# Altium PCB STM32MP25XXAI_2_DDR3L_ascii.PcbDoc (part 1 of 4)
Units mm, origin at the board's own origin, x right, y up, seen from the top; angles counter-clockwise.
Board outline 172 x 137 mm, 6 copper layers (Top Layer, Signal Layer 1, Signal Layer 2, Signal Layer 3, Signal Layer 4, Bottom Layer), stack 2.079 mm thick; 237 components, 152 nets, 1304 pads, 909 vias.
Unrouted connection lines stored in the file: 13.
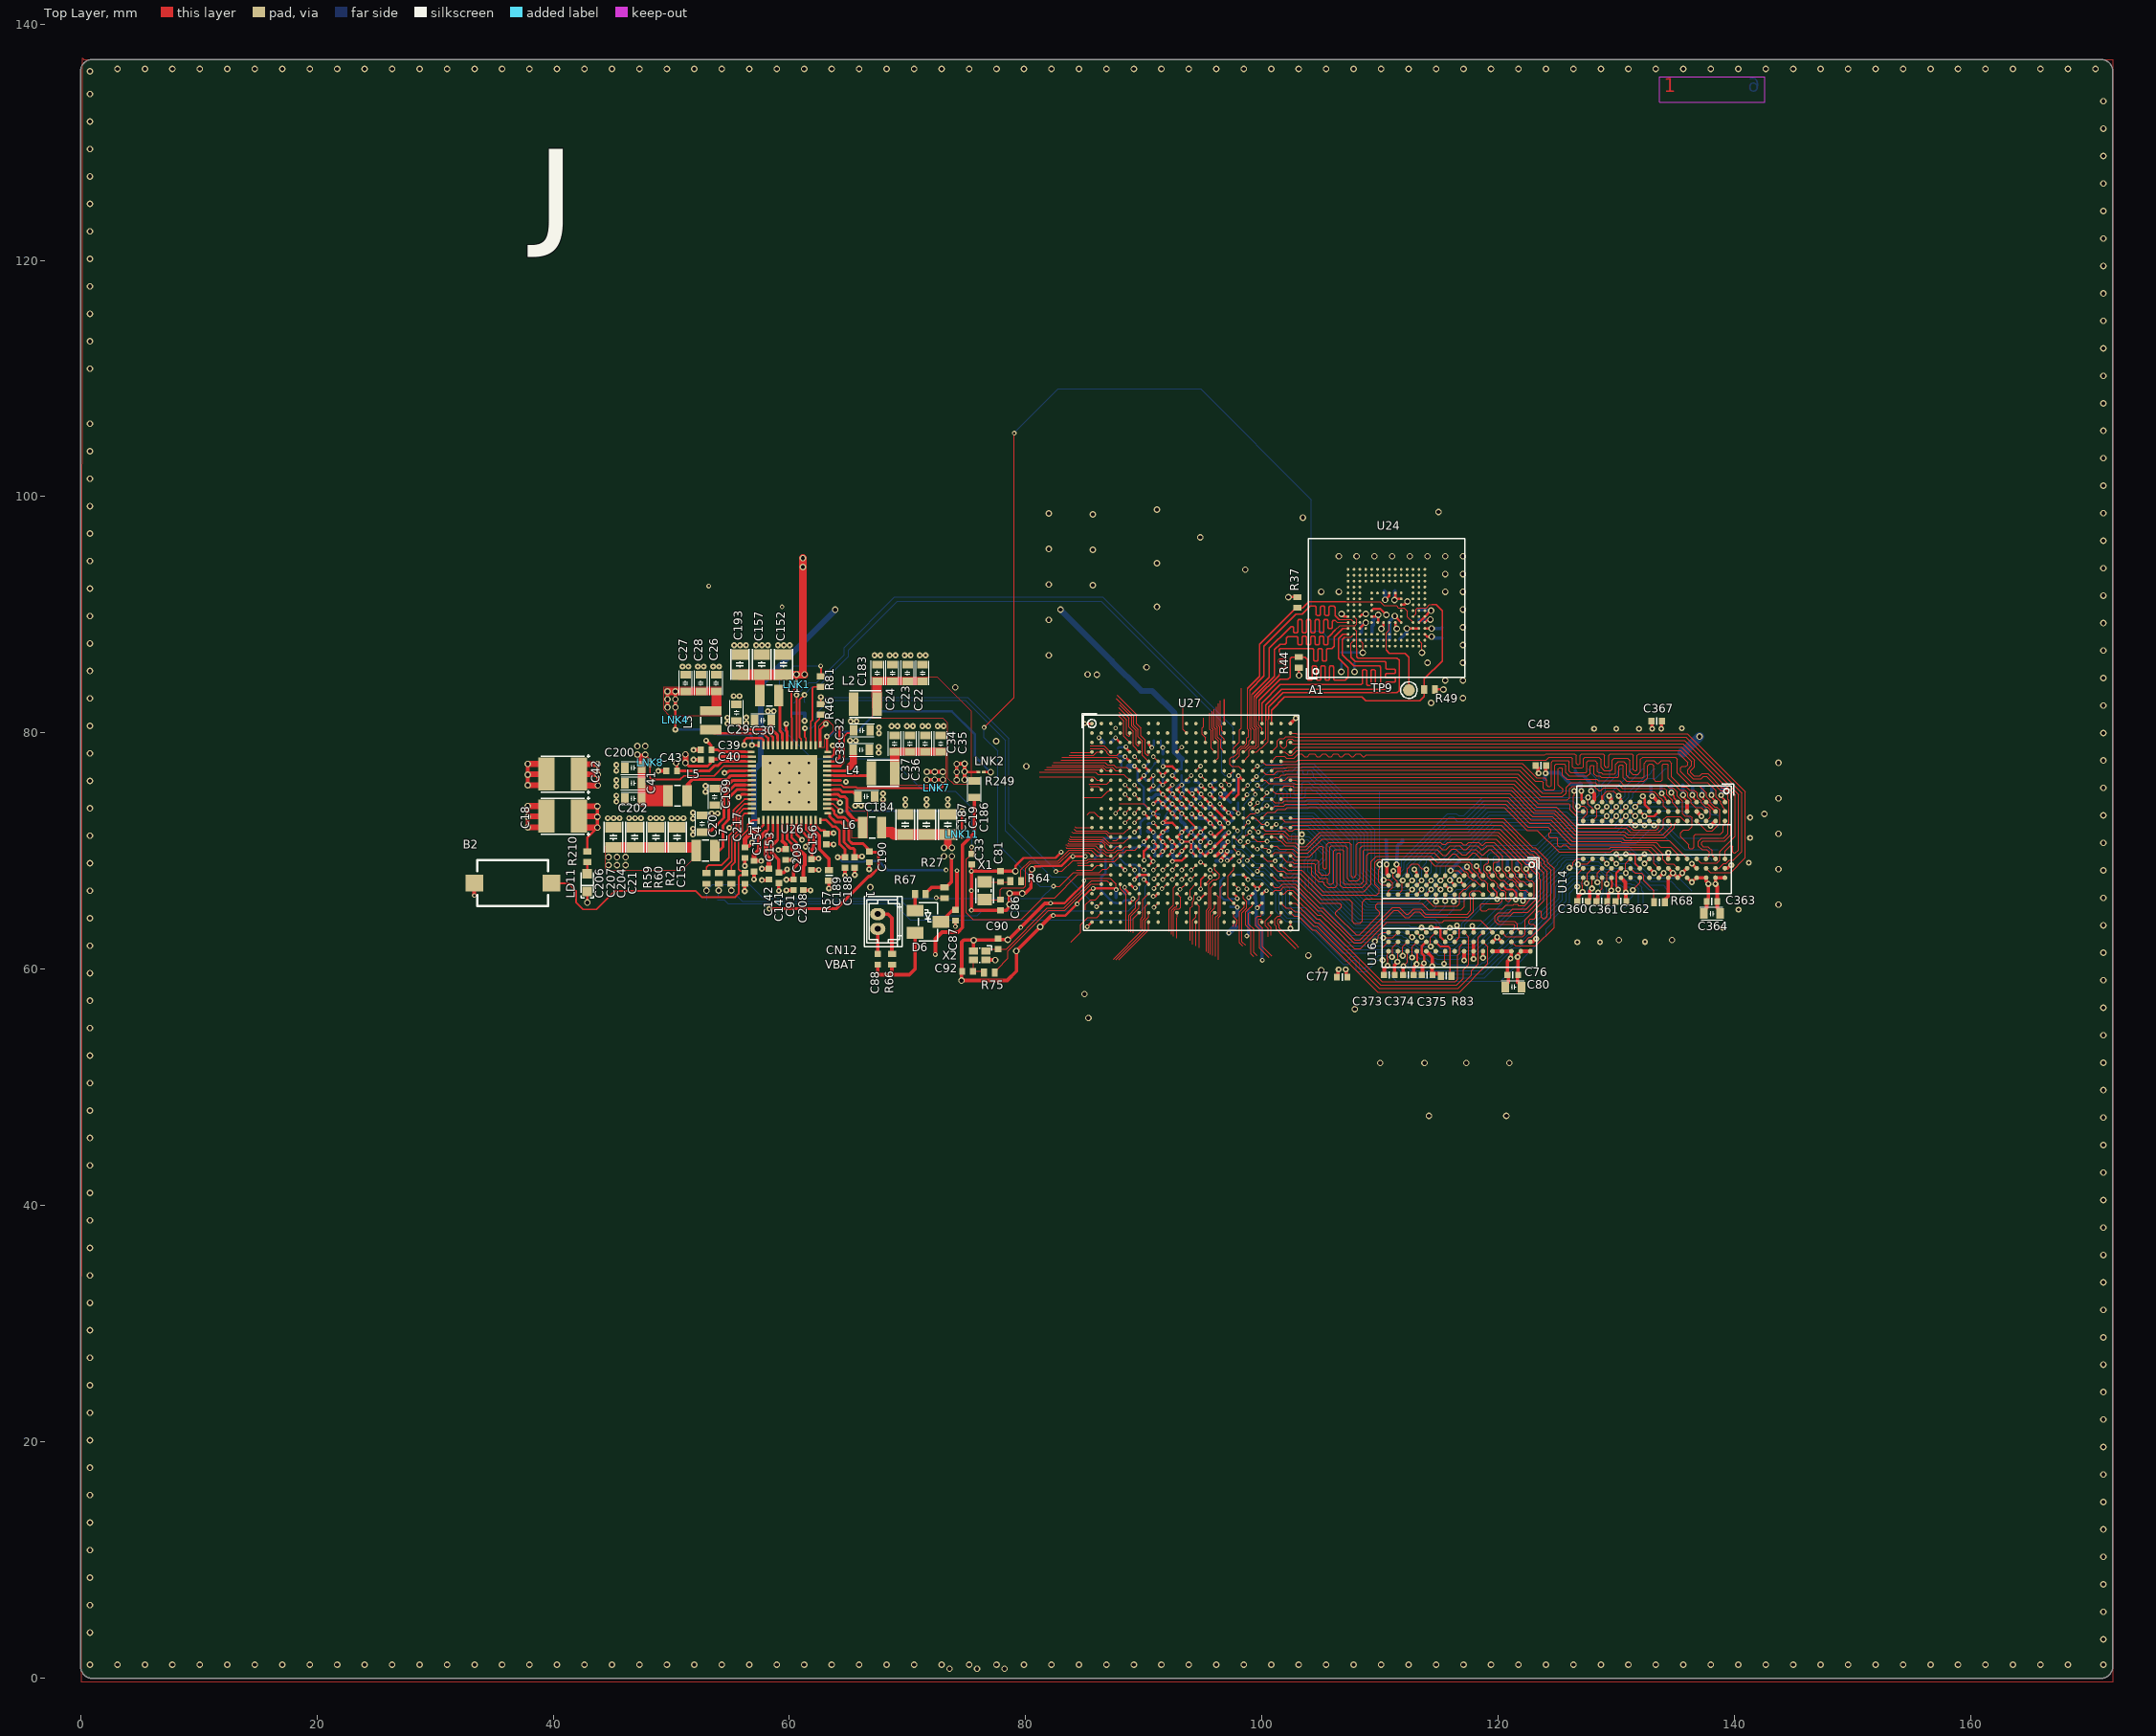
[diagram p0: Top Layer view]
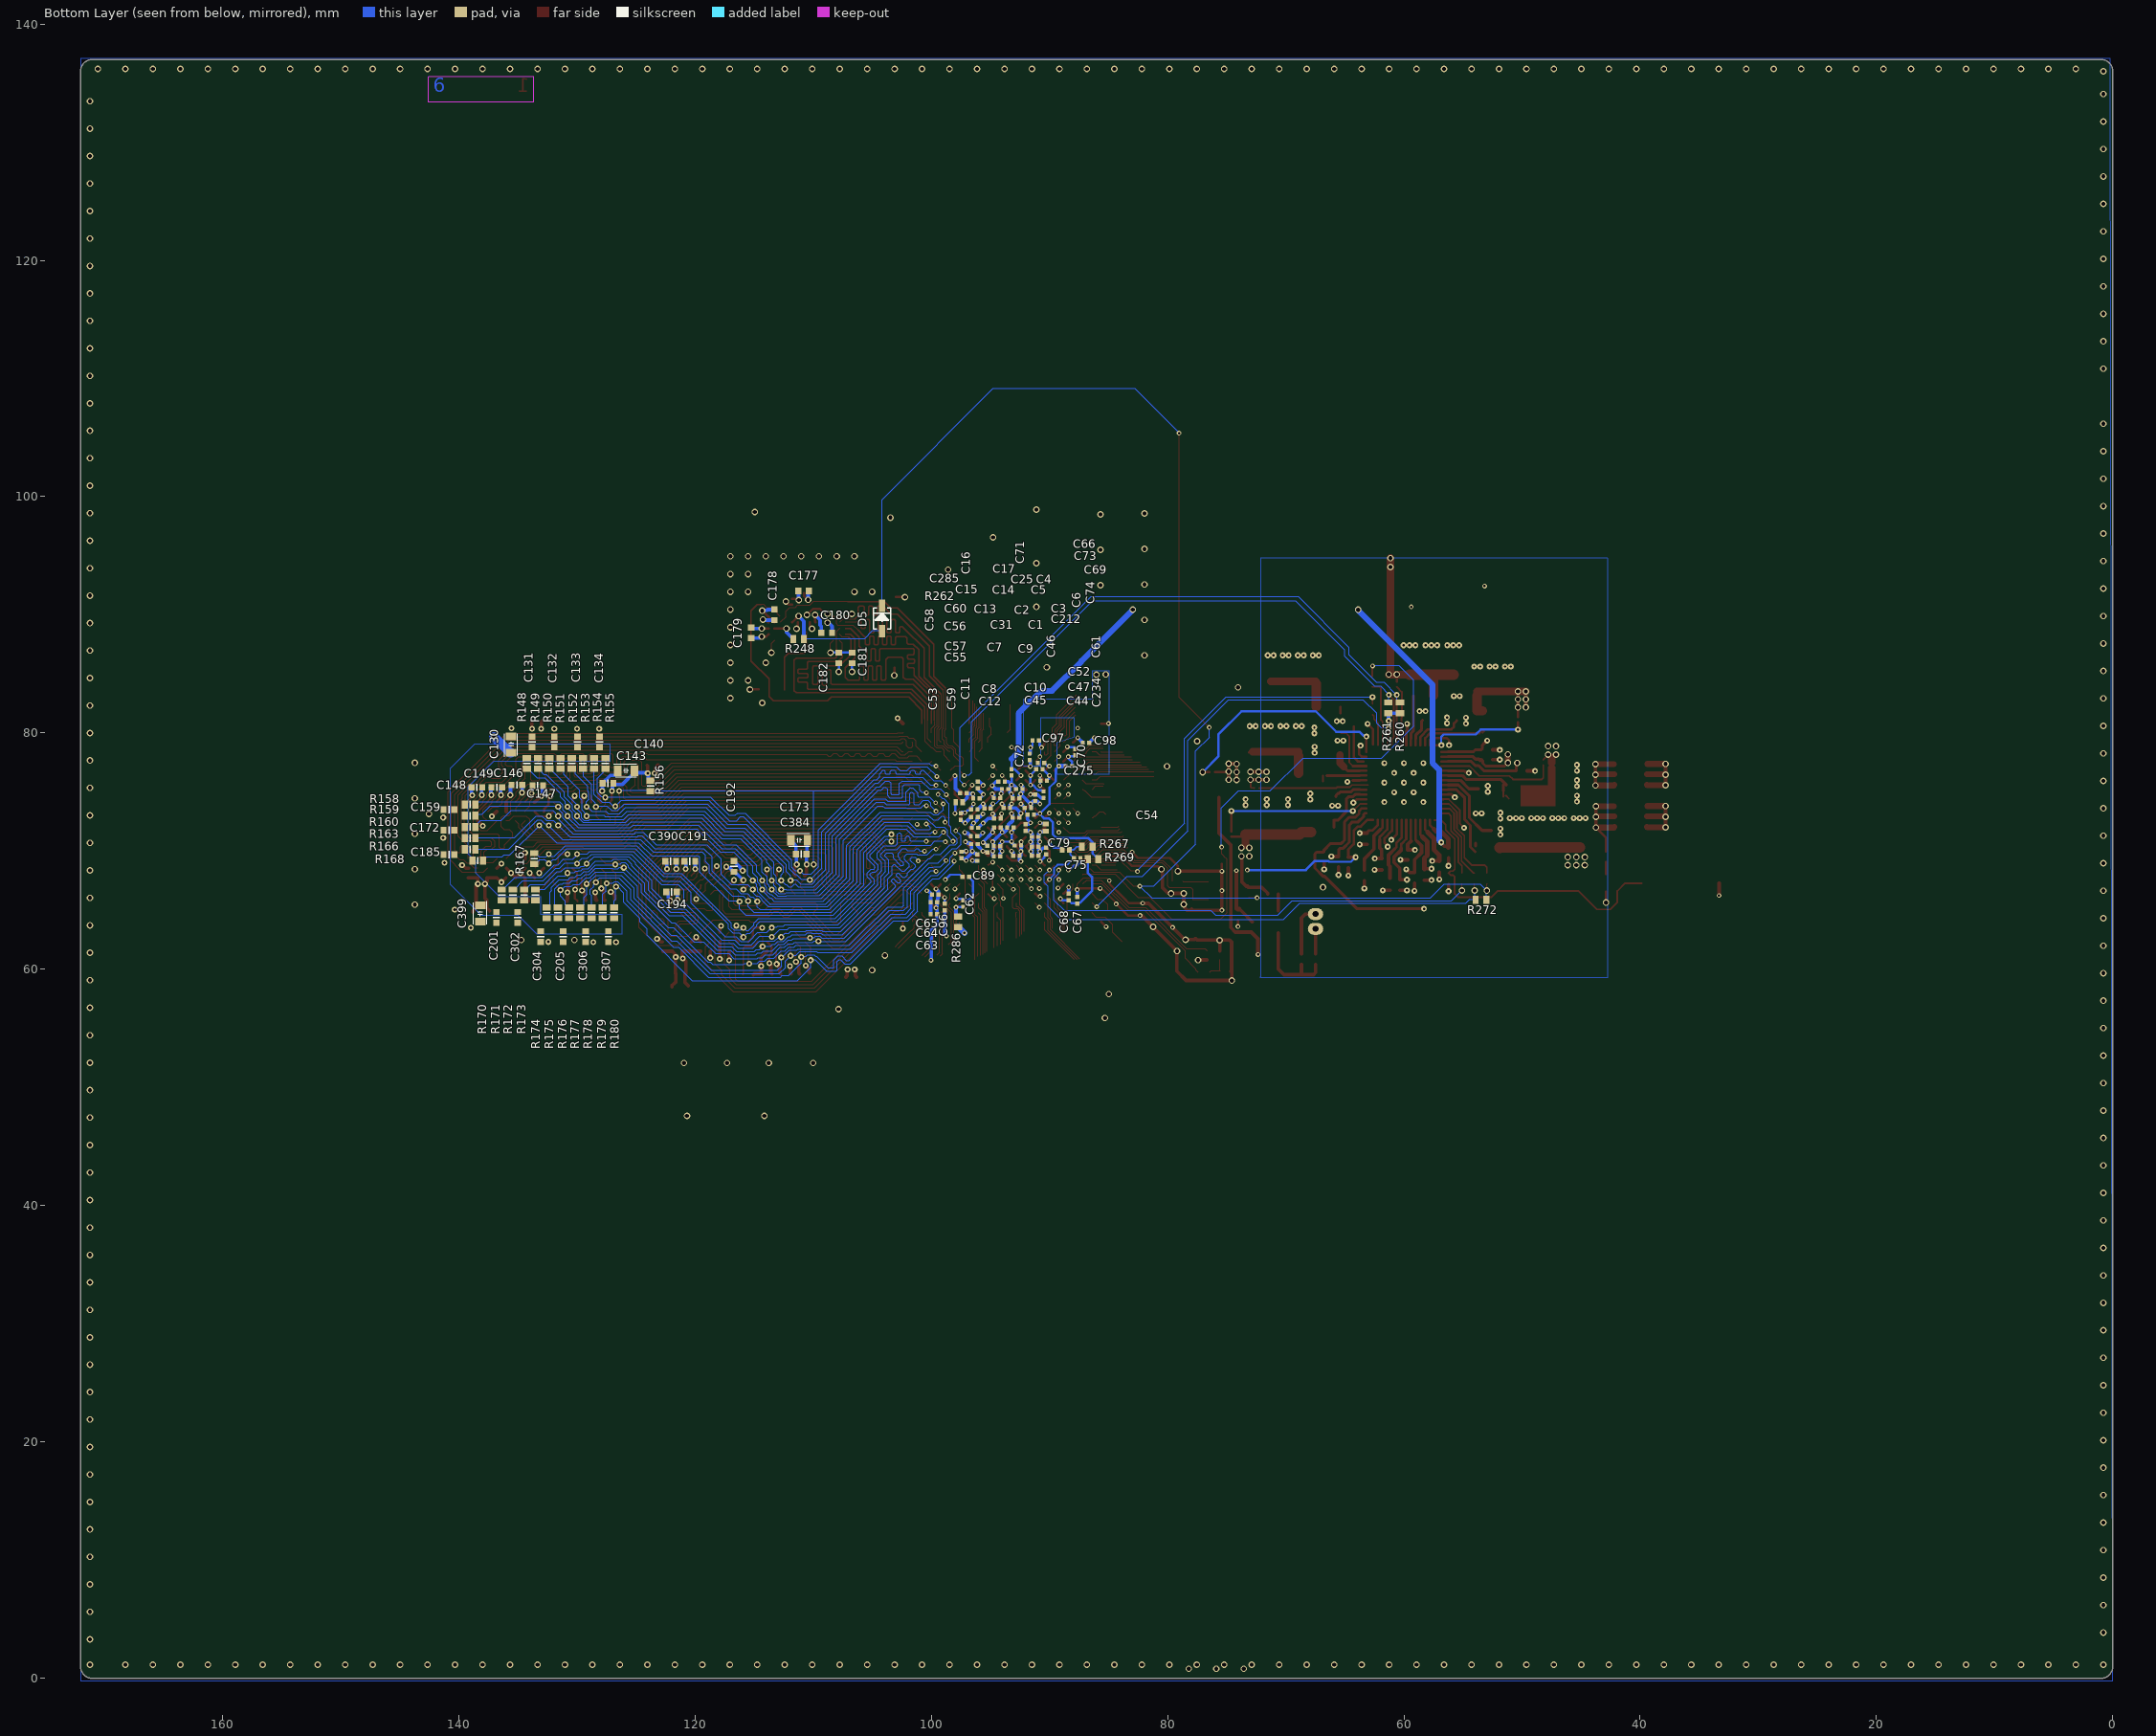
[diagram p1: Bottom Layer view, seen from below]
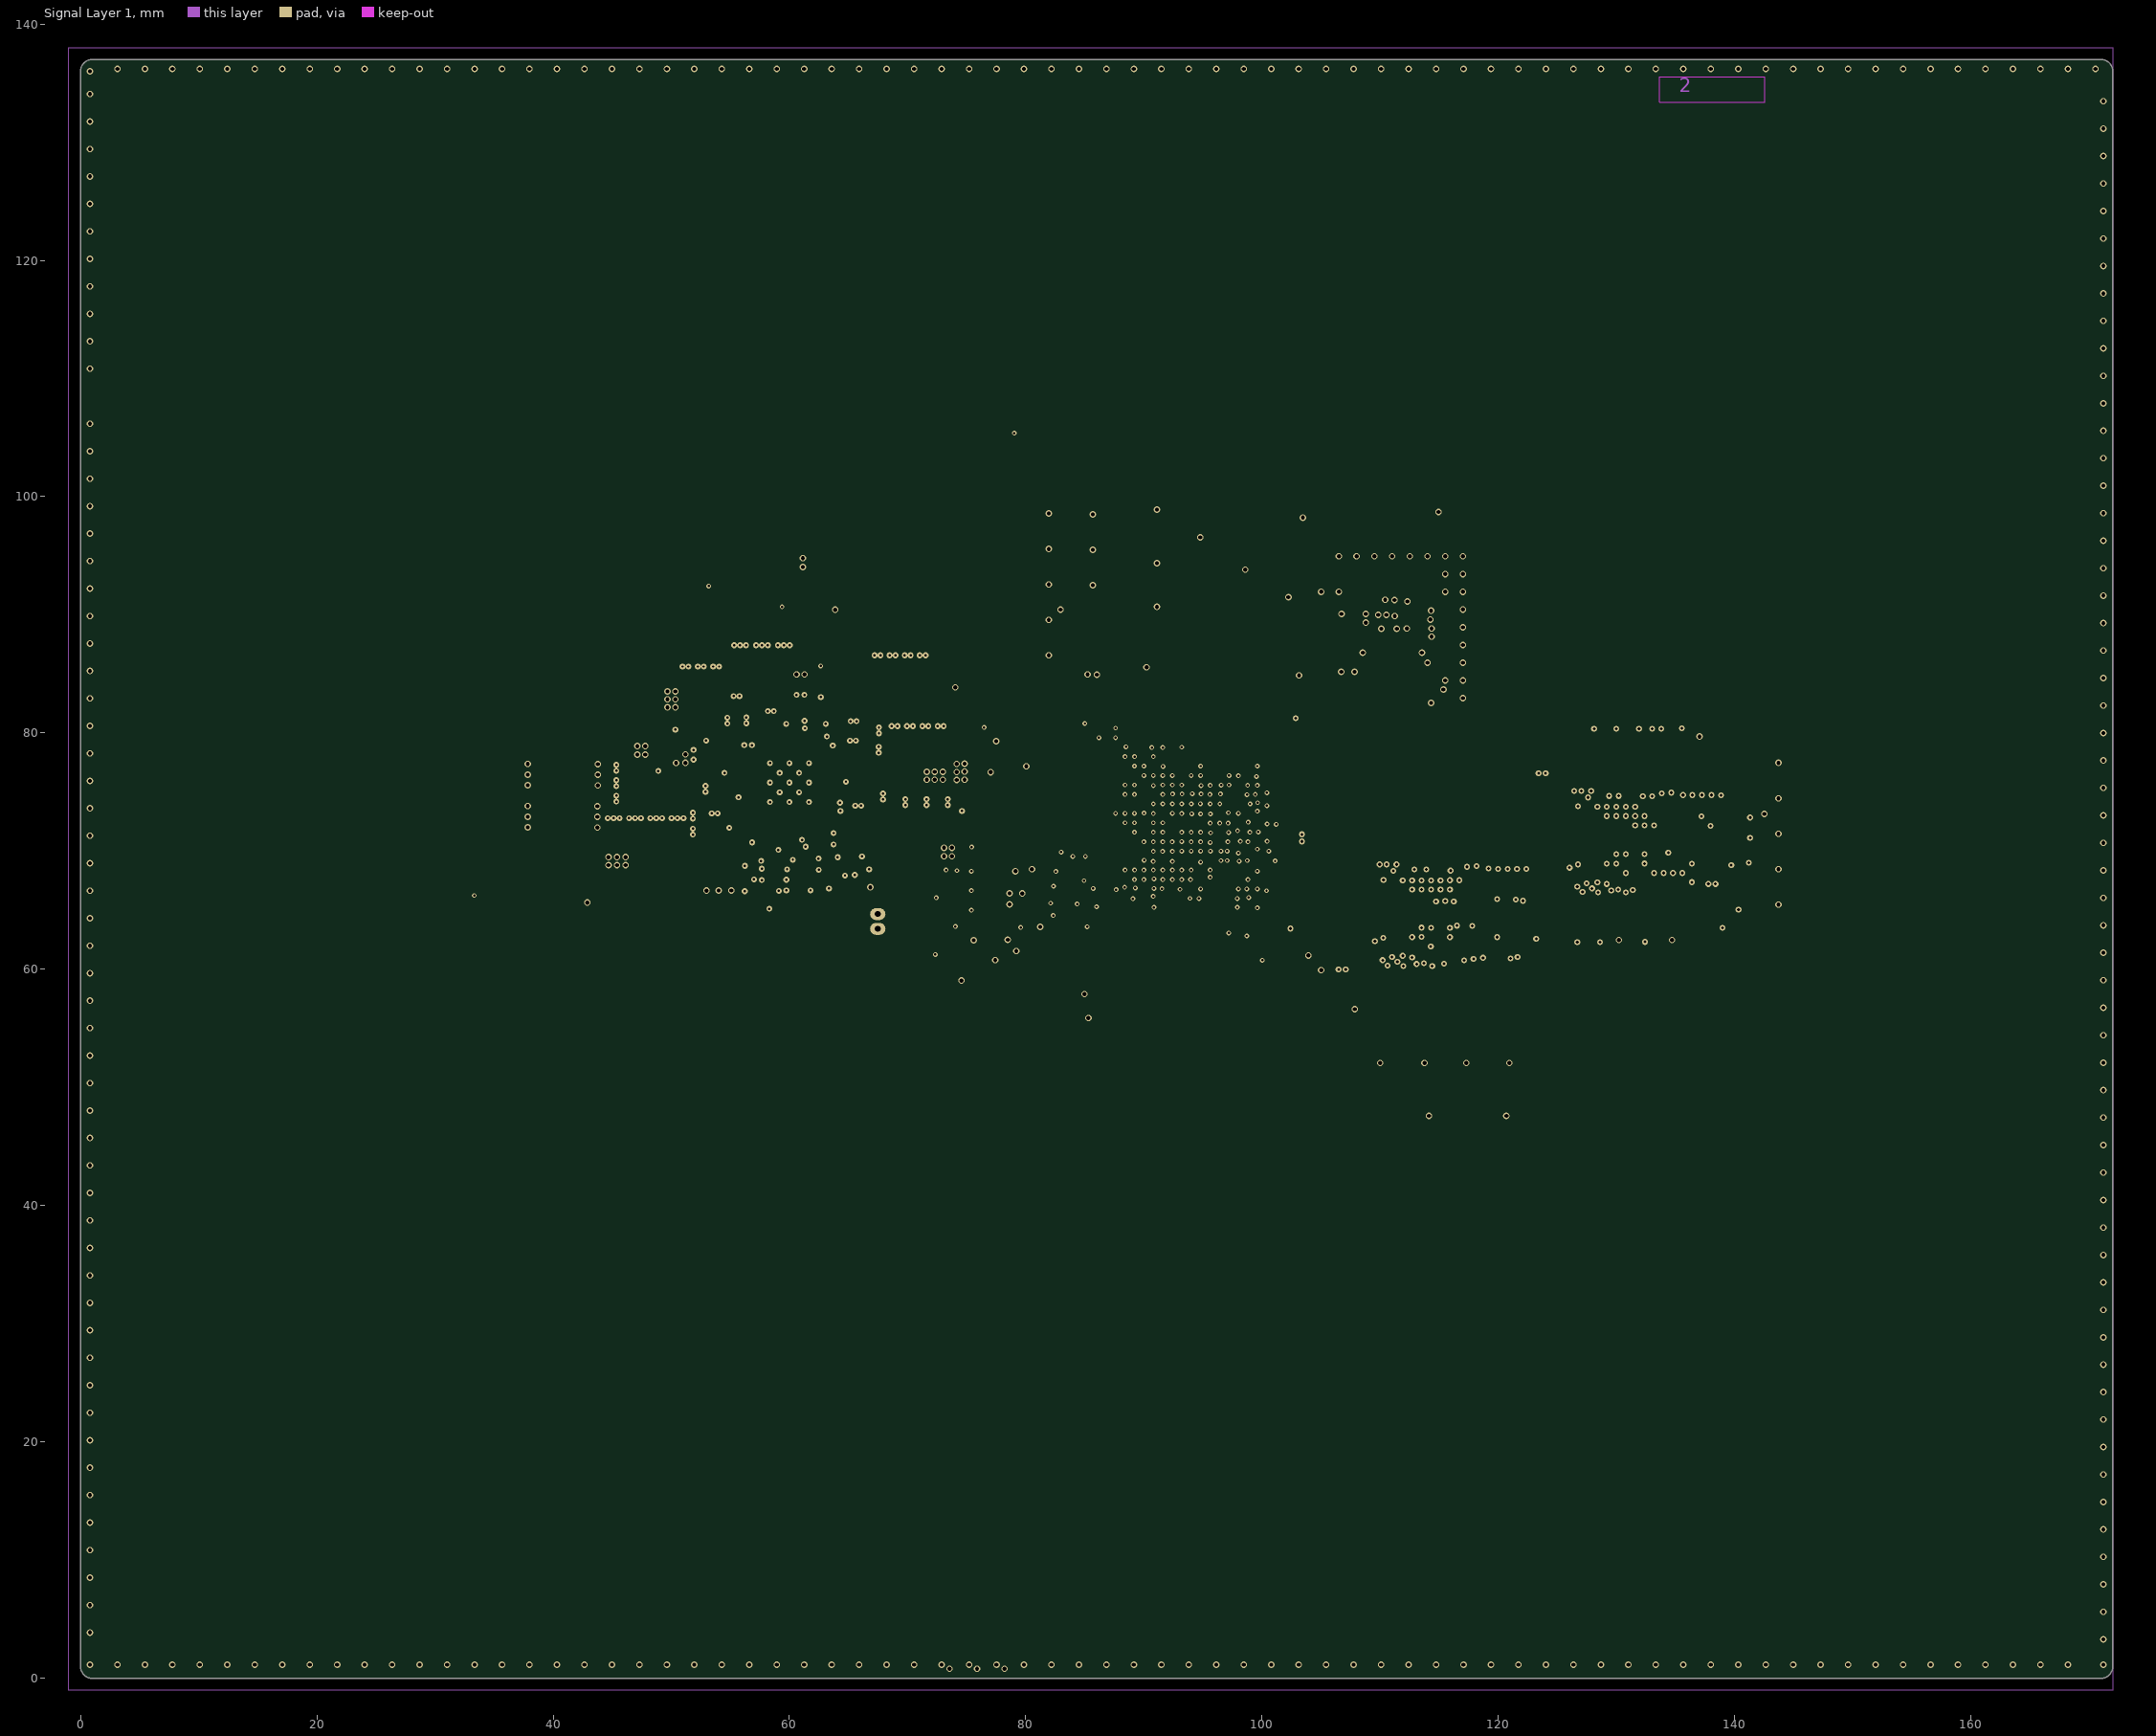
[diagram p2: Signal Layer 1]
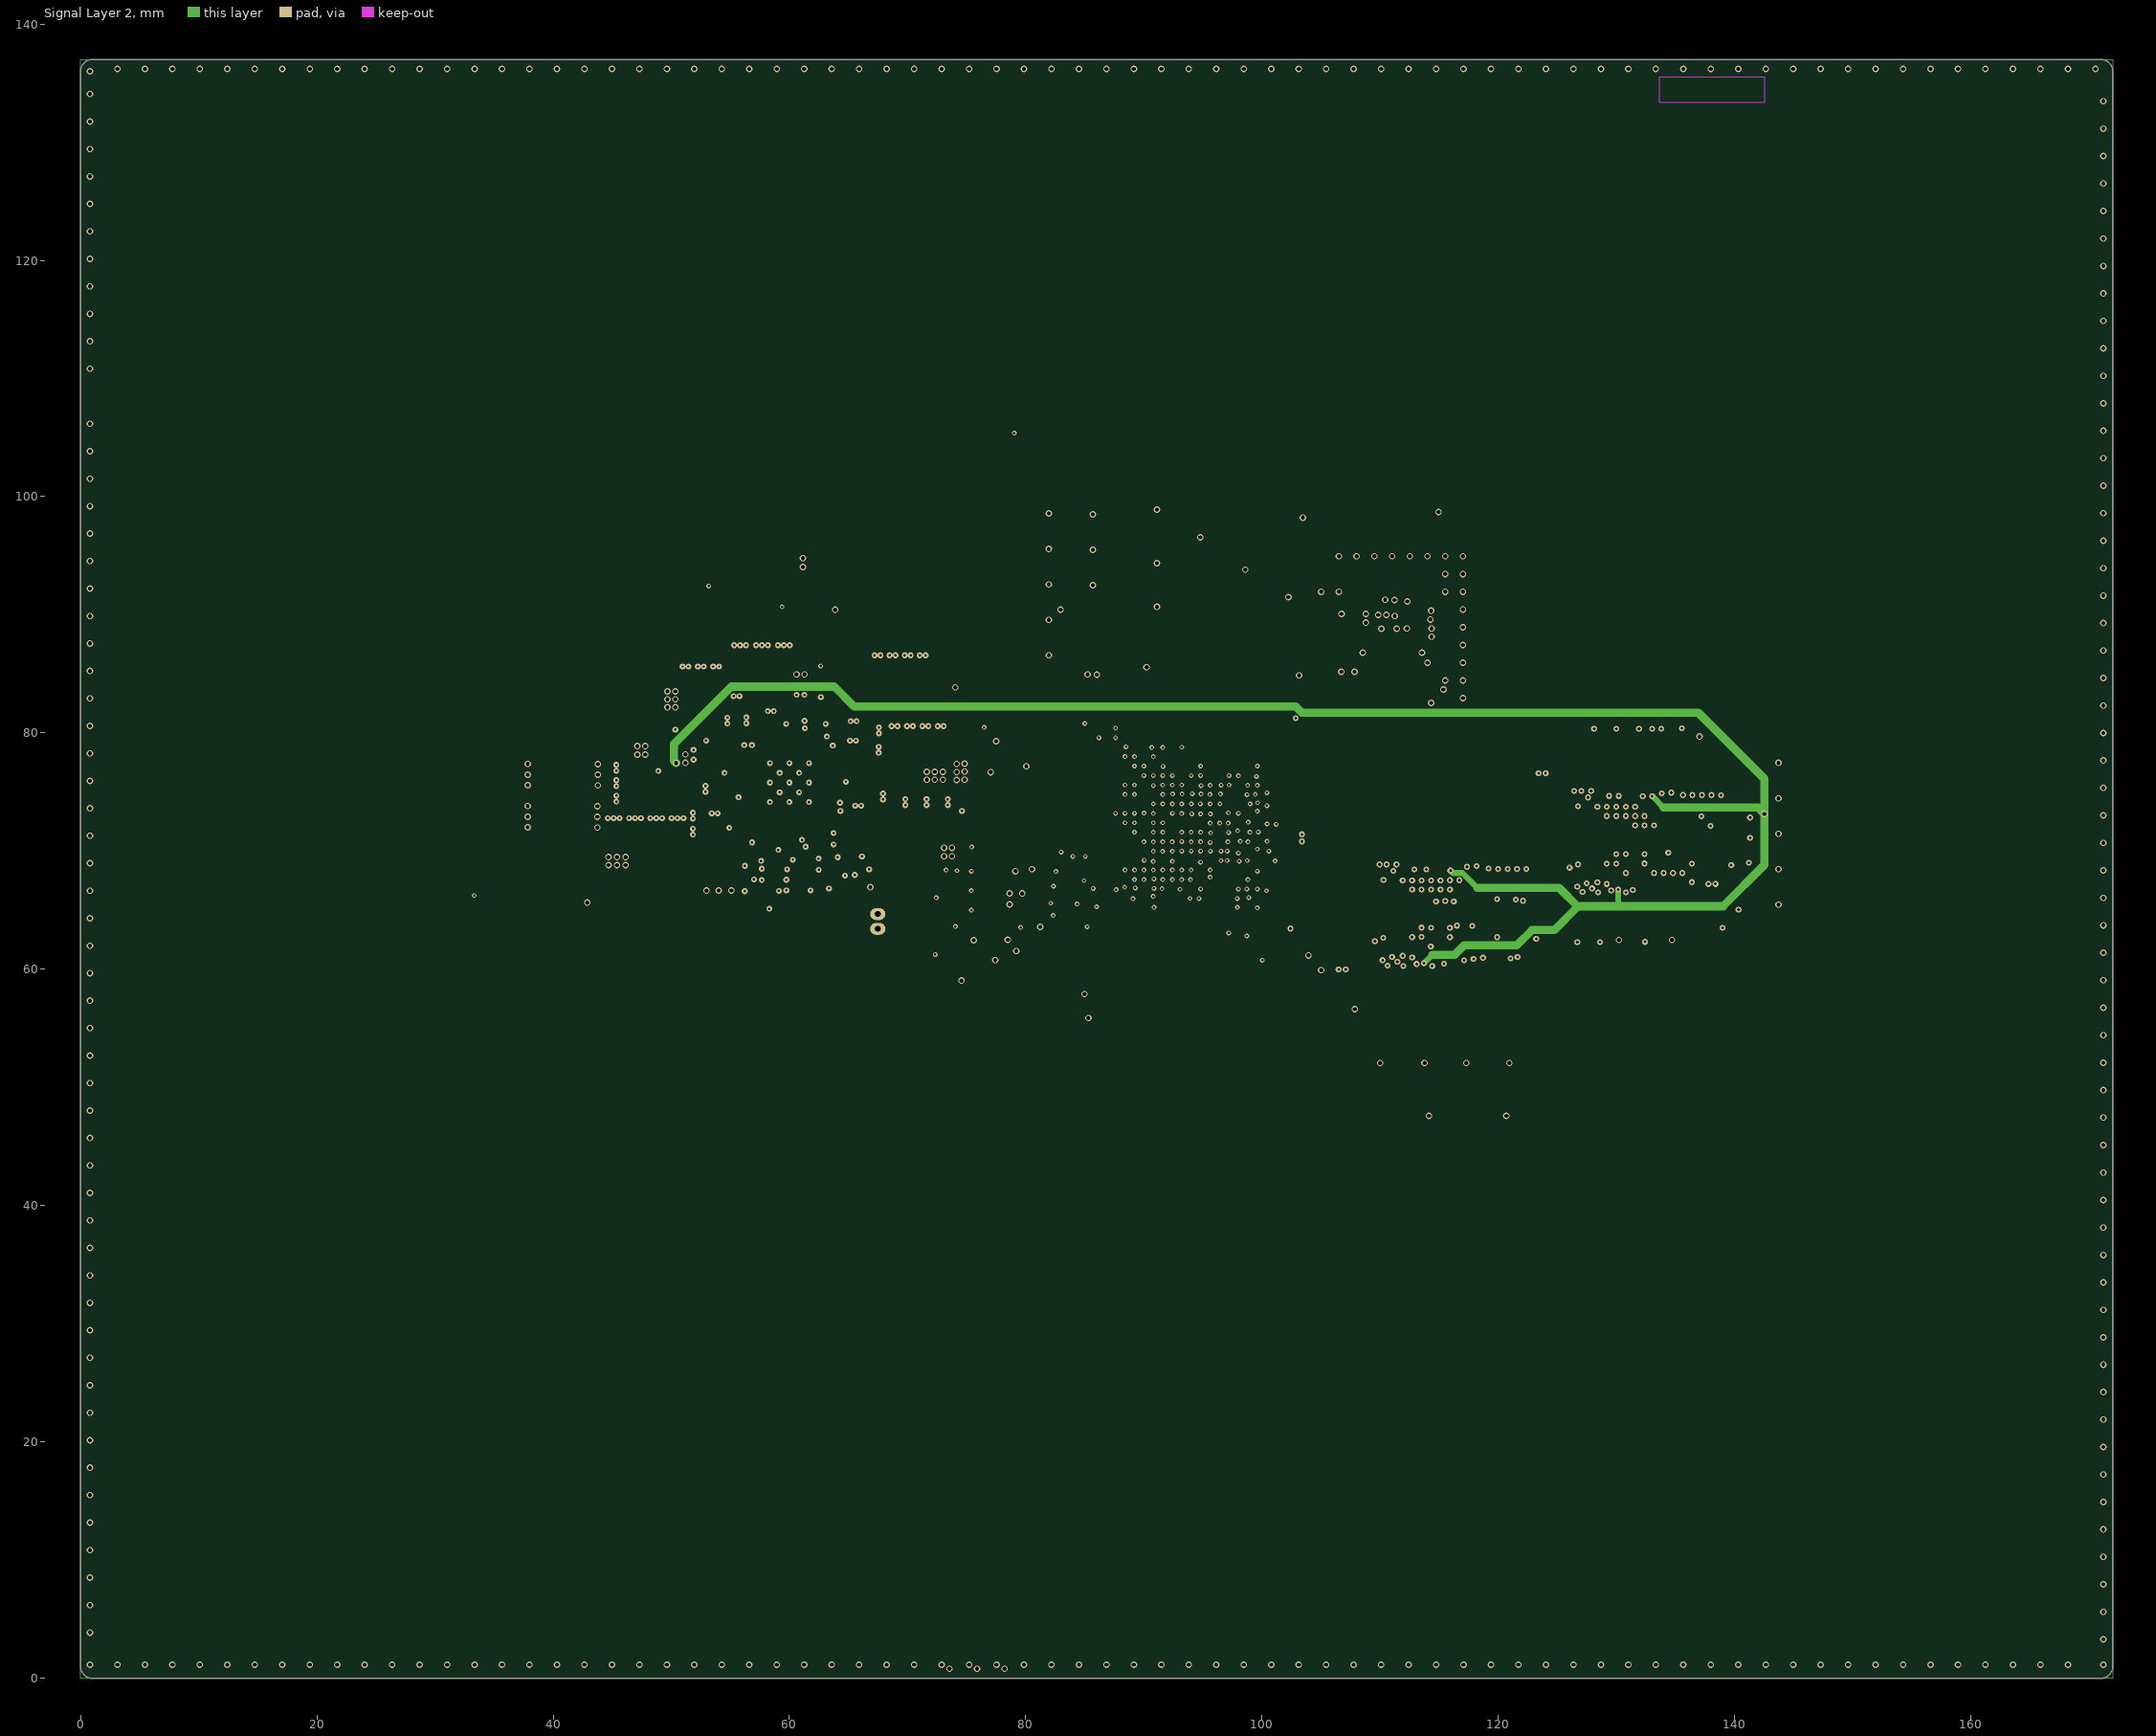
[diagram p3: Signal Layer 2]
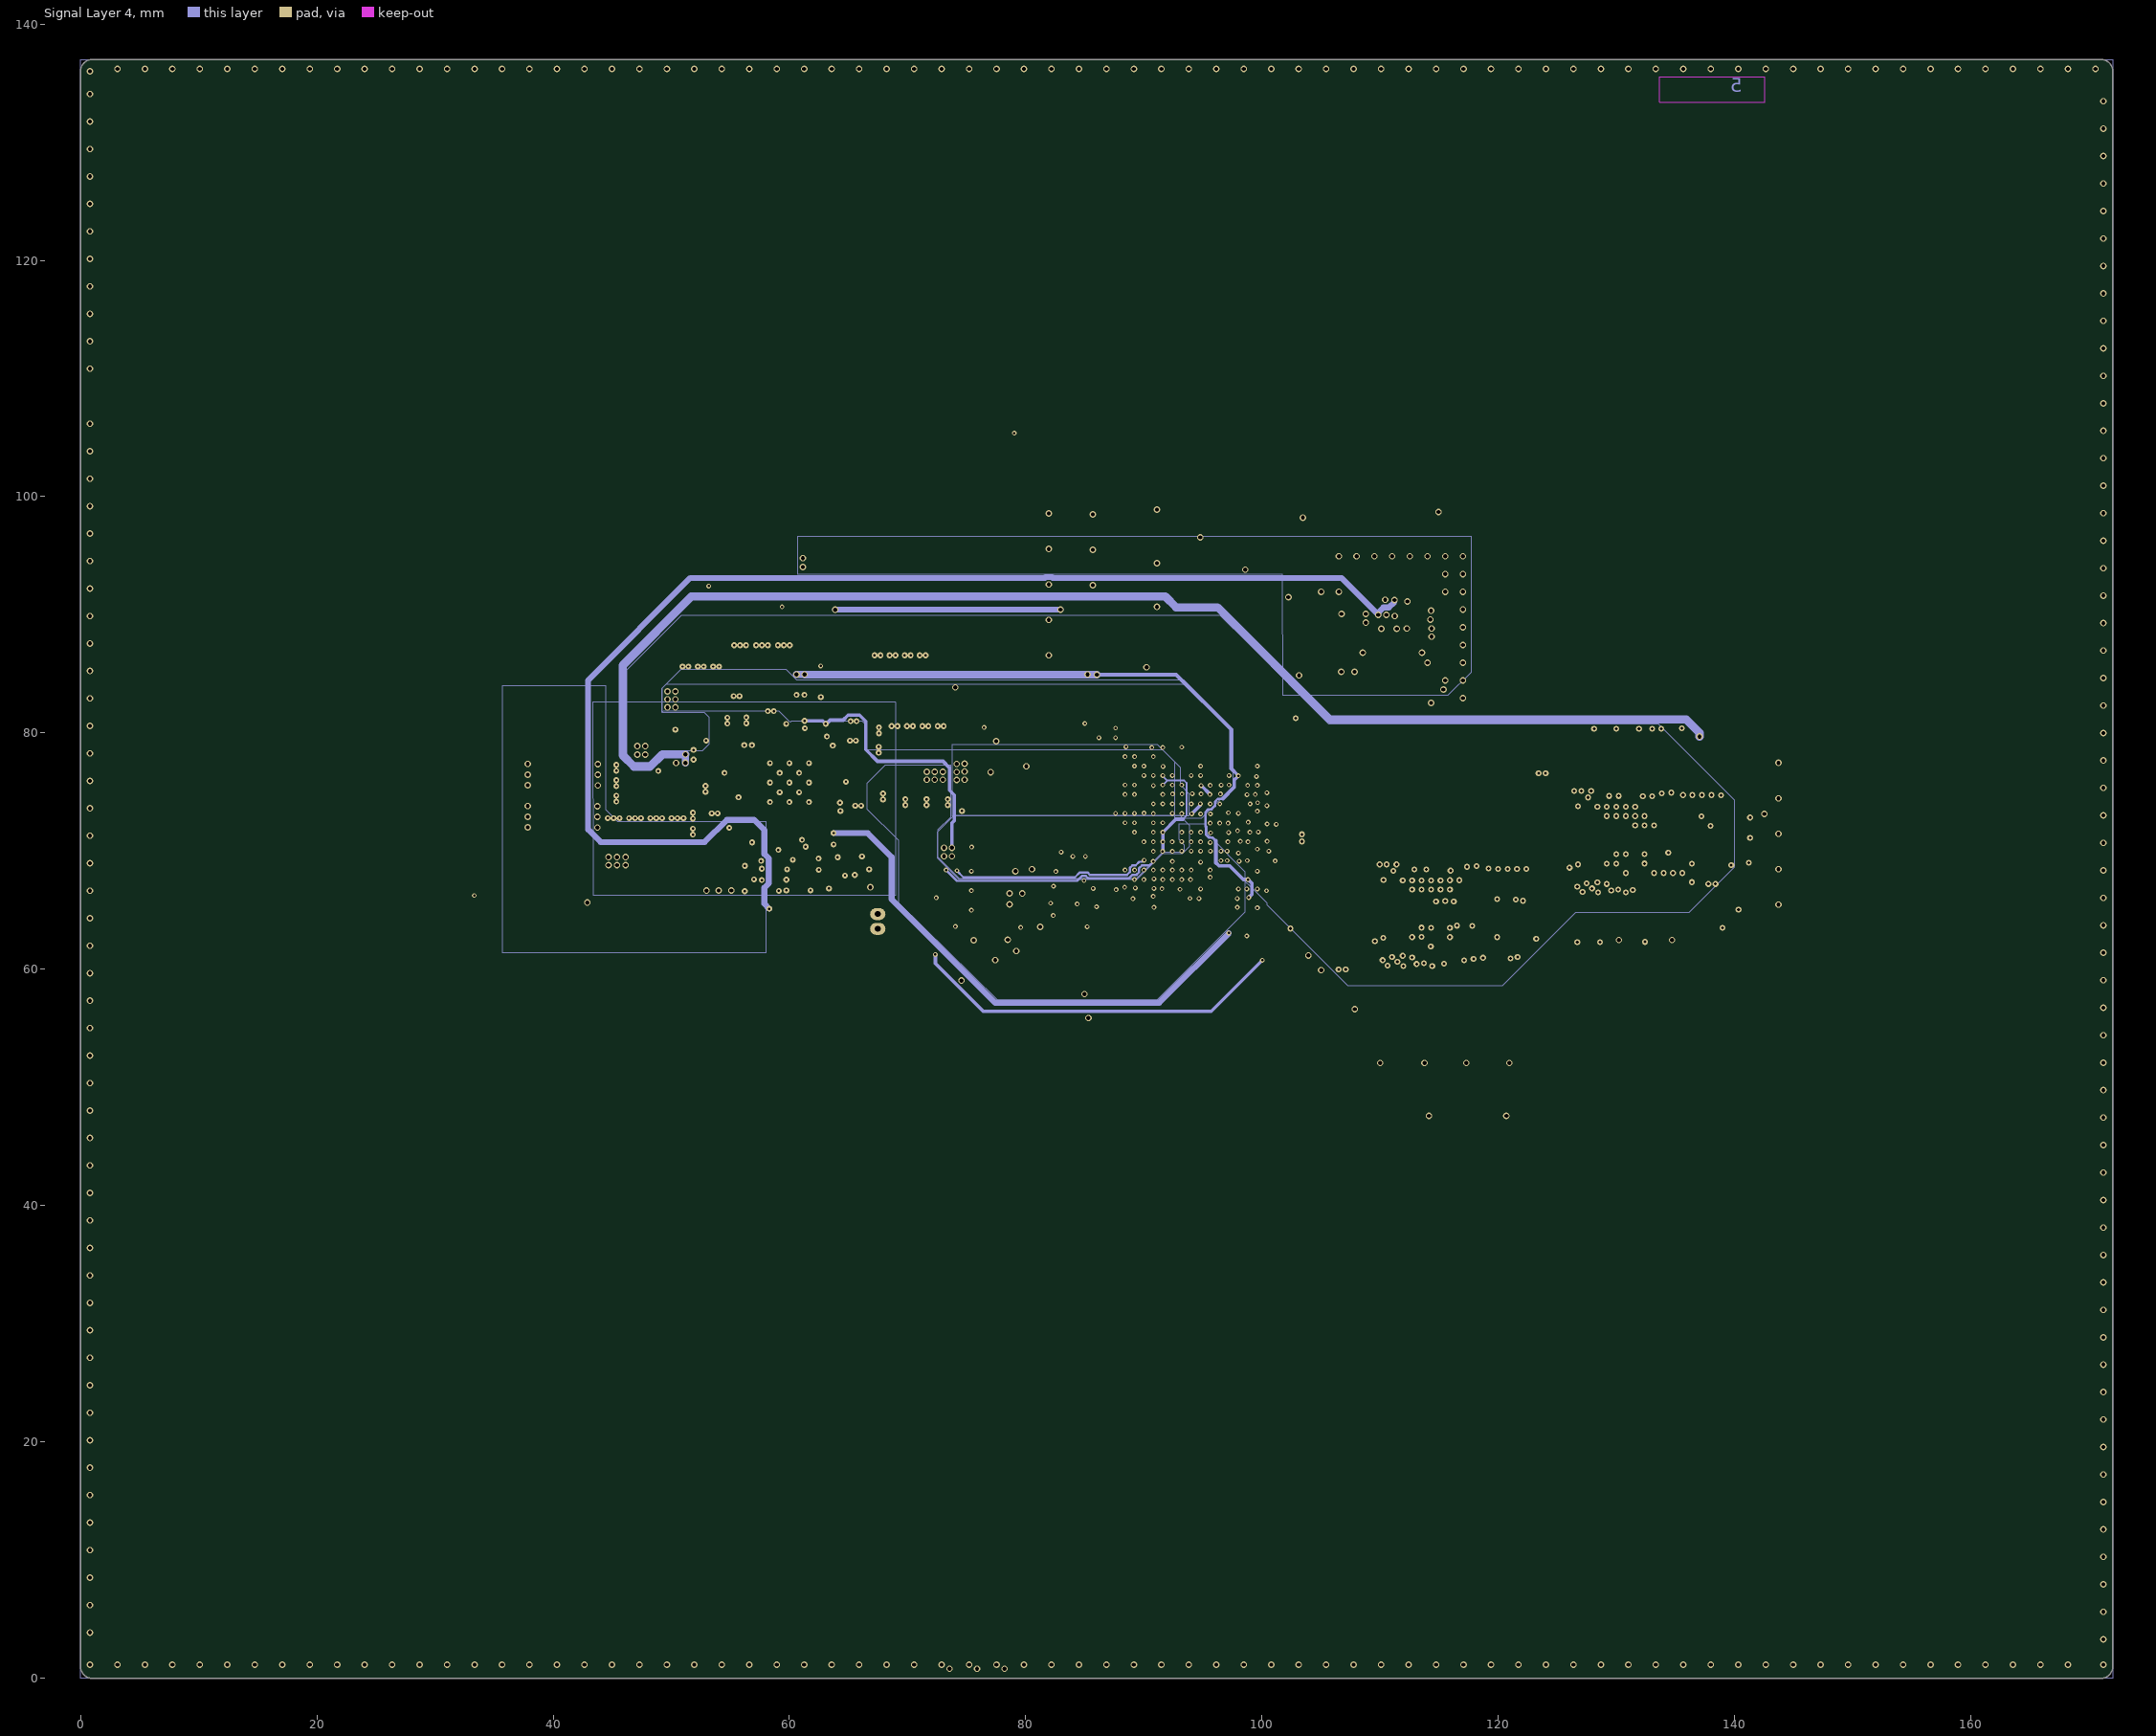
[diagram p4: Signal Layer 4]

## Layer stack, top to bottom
Top Solder: solder mask 0.025, Solder Resist, Dk 3.5
Top Layer: signal copper 0.037
Dielectric 1: prepreg 0.072, Dk 3.8
Signal Layer 1: signal copper 0.035
Dielectric 2: prepreg 0.5, Dk 5
Signal Layer 2: signal copper 0.3
Dielectric 3: core 0.191, Dk 4.3
Signal Layer 3: signal copper 0.3
Dielectric 4: prepreg 0.5, Dk 5
Signal Layer 4: signal copper 0.035
Dielectric 5: prepreg 0.072, Dk 3.8
Bottom Layer: signal copper 0.037
Bottom Solder: solder mask 0.025, Solder Resist, Dk 3.5

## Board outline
0,1 0,95 0,136 cw(c1,136) 1,137 171,137 cw(c171,136) 172,136 172,1 cw(c171,1) 171,0 1,0 cw(c1,1)

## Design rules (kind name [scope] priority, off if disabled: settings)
AssemblyTestPointUsage [All] p0: scope1count=1 scope1_0_kind=Board scope1_0_value=Board scope2count=1 scope2_0_kind=Board scope2_0_value=Board commentlength=0
AssemblyTestpoint [All] p0: scope1count=1 scope1_0_kind=Board scope1_0_value=Board scope2count=1 scope2_0_kind=Board scope2_0_value=Board commentlength=0
BoardOutlineClearance Silkscreen [All] p0 off: scope1count=1 scope1_0_kind=Board scope1_0_value=Board scope2count=1 scope2_0_kind=Board scope2_0_value=Board commentlength=90 gap=0 // Protel DXP Scope 1 Expression Was: OnLayer('Top Overlay') or OnLayer('Bottom Overlay')
BoardOutlineClearance [All] p0: scope1count=1 scope1_0_kind=Board scope1_0_value=Board scope2count=1 scope2_0_kind=Board scope2_0_value=Board commentlength=0 gap=0.5
BoardOutlineClearance Silkscreen [OnLayer('Top Overlay') or OnLayer('Bottom Overlay')] p1: gap=0 ignorepadtopadclearanceinfootprint=FALSE
BoardOutlineClearance [All] p2: gap=0.5 ignorepadtopadclearanceinfootprint=FALSE
Clearance Clearance_Default [All] p0: scope1count=1 scope1_0_kind=Board scope1_0_value=Board scope2count=1 scope2_0_kind=Board scope2_0_value=Board commentlength=0 gap=0.1
Clearance Clearance_Default [All] p1: gap=0.1 ignorepadtopadclearanceinfootprint=TRUE except(0: Arc-Hole Track-Hole SMDPad-Hole THPad-Hole Via-Hole Fill-Hole Poly-Hole Region-Hole Text-Hole; 0.09: Track-Track Track-SMDPad)
ComponentClearance [All] p0 off: scope1count=1 scope1_0_kind=Board scope1_0_value=Board scope2count=1 scope2_0_kind=Board scope2_0_value=Board commentlength=0 gap=0.2 collisioncheckmode=3
ComponentClearance [All] p1 off: gap=0.2 collisioncheckmode=3 verticalgap=0 showdistances=FALSE
DiffPairsRouting DiffPairsRouting_DDR_100R [All] p0 off: scope1count=1 scope1_0_kind=Board scope1_0_value=Board scope2count=1 scope2_0_kind=Board scope2_0_value=Board commentlength=78 // Protel DXP Scope 1 Expression Was: InDifferentialPairClass('DPC_DDR_100R')
DiffPairsRouting DiffPairsRouting_DDR_100R [InDifferentialPairClass('DPC_DDR_100R')] p1: maxlimit=254 minlimit=0.127 mostfreqgap=0.254 toplayer_mingap=0.16 toplayer_maxgap=0.16 toplayer_prefgap=0.16 toplayer_minwidth=0.09 toplayer_maxwidth=0.09 toplayer_prefwidth=0.09 midlayer1_mingap=0.14 midlayer1_maxgap=0.254 midlayer1_minwidth=0.381 midlayer1_maxwidth=0.381 midlayer1_prefwidth=0.381 midlayer2_maxgap=0.16 midlayer2_prefgap=0.127 midlayer2_minwidth=0.381 midlayer2_maxwidth=0.381 midlayer2_prefwidth=0.381 midlayer3_maxgap=0.16 midlayer3_prefgap=0.127 midlayer3_minwidth=0.381 midlayer3_maxwidth=0.381 midlayer3_prefwidth=0.381 midlayer4_mingap=0.14 midlayer4_minwidth=0.381 midlayer4_maxwidth=0.381 midlayer4_prefwidth=0.381 bottomlayer_mingap=0.16 bottomlayer_maxgap=0.16 bottomlayer_prefgap=0.16 bottomlayer_minwidth=0.09 bottomlayer_maxwidth=0.09 bottomlayer_prefwidth=0.09 maxuncoupledlength=12.7
FabricationTestPointUsage [All] p0: scope1count=1 scope1_0_kind=Board scope1_0_value=Board scope2count=1 scope2_0_kind=Board scope2_0_value=Board commentlength=0 valid=0 allowmultiple=FALSE
FabricationTestpoint [All] p0: scope1count=1 scope1_0_kind=Board scope1_0_value=Board scope2count=1 scope2_0_kind=Board scope2_0_value=Board commentlength=0 side=3 testpointundercomponent=TRUE minsize=1.016 maxsize=2.54 preferedsize=1.524 minholesize=0 maxholesize=1.016 preferedholesize=0.813 testpointgrid=0.025
FanoutControl Fanout_Default [All] p0: scope1count=1 scope1_0_kind=Board scope1_0_value=Board scope2count=1 scope2_0_kind=Board scope2_0_value=Board commentlength=30 // Fanout_Default (Default Rule)
FanoutControl Fanout_Small [All] p0 off: scope1count=1 scope1_0_kind=Board scope1_0_value=Board scope2count=1 scope2_0_kind=Board scope2_0_value=Board commentlength=84 // Protel DXP Scope 1 Expression Was: (CompPinCount < 5)   Fanout_Small (Default Rule)
FanoutControl Fanout_SOIC [All] p0 off: scope1count=1 scope1_0_kind=Board scope1_0_value=Board scope2count=1 scope2_0_kind=Board scope2_0_value=Board commentlength=71 // Protel DXP Scope 1 Expression Was: IsSOIC   Fanout_SOIC (Default Rule)
FanoutControl Fanout_LCC [All] p0 off: scope1count=1 scope1_0_kind=Board scope1_0_value=Board scope2count=1 scope2_0_kind=Board scope2_0_value=Board commentlength=69 // Protel DXP Scope 1 Expression Was: IsLCC   Fanout_LCC (Default Rule)
FanoutControl Fanout_BGA [All] p0 off: scope1count=1 scope1_0_kind=Board scope1_0_value=Board scope2count=1 scope2_0_kind=Board scope2_0_value=Board commentlength=69 // Protel DXP Scope 1 Expression Was: IsBGA   Fanout_BGA (Default Rule)
FanoutControl Fanout_BGA [IsBGA] p1: bgadir=Out bgaviamode=Closest fanoutstyle=Auto fanoutdirection=Alternating viagrid=0.025 // Fanout_BGA (Default Rule)
FanoutControl Fanout_LCC [IsLCC] p2: bgadir=Out bgaviamode=Closest fanoutstyle=Auto fanoutdirection=Alternating viagrid=0.025 // Fanout_LCC (Default Rule)
FanoutControl Fanout_SOIC [IsSOIC] p3: bgadir=Out bgaviamode=Closest fanoutstyle=Auto fanoutdirection=Alternating viagrid=0.025 // Fanout_SOIC (Default Rule)
FanoutControl Fanout_Small [(CompPinCount < 5)] p4: bgadir=Out bgaviamode=Closest fanoutstyle=Auto fanoutdirection=OutThenIn viagrid=0.025 // Fanout_Small (Default Rule)
FanoutControl Fanout_Default [All] p5: bgadir=Out bgaviamode=Closest fanoutstyle=Auto fanoutdirection=Alternating viagrid=0.025 // Fanout_Default (Default Rule)
Height [All] p0: scope1count=1 scope1_0_kind=Board scope1_0_value=Board scope2count=1 scope2_0_kind=Board scope2_0_value=Board commentlength=0
HoleSize [All] p0: scope1count=1 scope1_0_kind=Board scope1_0_value=Board scope2count=1 scope2_0_kind=Board scope2_0_value=Board commentlength=0 absolutevalues=TRUE maxlimit=10 minlimit=0.025 maxpercent=80.000 minpercent=20.000
HoleSize [All] p1: absolutevalues=TRUE maxlimit=10 minlimit=0.025 maxpercent=80.000 minpercent=20.000
HoleToHoleClearance [All] p0: scope1count=1 scope1_0_kind=Board scope1_0_value=Board scope2count=1 scope2_0_kind=Board scope2_0_value=Board commentlength=0
HoleToHoleClearance [All] p1: gap=0.25 allowstackedmicrovias=TRUE
LayerPairs [All] p0: scope1count=1 scope1_0_kind=Board scope1_0_value=Board scope2count=1 scope2_0_kind=Board scope2_0_value=Board commentlength=0 enforce=TRUE
MinimumSolderMaskSliver [All] p0: scope1count=1 scope1_0_kind=Board scope1_0_value=Board scope2count=1 scope2_0_kind=Board scope2_0_value=Board commentlength=0
MinimumSolderMaskSliver [All] p1: minsoldermaskwidth=0.07
NetAntennae [All] p0: scope1count=1 scope1_0_kind=Board scope1_0_value=Board scope2count=1 scope2_0_kind=Board scope2_0_value=Board commentlength=0
PasteMaskExpansion [All] p0: scope1count=1 scope1_0_kind=Board scope1_0_value=Board scope2count=1 scope2_0_kind=Board scope2_0_value=Board commentlength=0 expansion=0
PlaneClearance [All] p0: scope1count=1 scope1_0_kind=Board scope1_0_value=Board scope2count=1 scope2_0_kind=Board scope2_0_value=Board commentlength=0 clearance=0.508
PlaneConnect [All] p0: scope1count=1 scope1_0_kind=Board scope1_0_value=Board scope2count=1 scope2_0_kind=Board scope2_0_value=Board commentlength=0 planeconnectstyle=Direct reliefexpansion=0.508 reliefentries=4 reliefconductorwidth=0.21 reliefairgap=0.21
PlaneConnect [All] p1: planeconnectstyle=Direct reliefexpansion=0.508 reliefentries=4 reliefconductorwidth=0.21 reliefairgap=0.21
PolygonConnect PolygonConnect_Default [All] p0: scope1count=1 scope1_0_kind=Board scope1_0_value=Board scope2count=1 scope2_0_kind=Board scope2_0_value=Board commentlength=0 connectstyle=Direct reliefconductorwidth=0.25 reliefentries=4 polygonreliefangle="90 Angle"
PolygonConnect PolygonConnect_Default [All] p1: connectstyle=Direct reliefconductorwidth=0.25 reliefentries=4 polygonreliefangle="90 Angle" airgapwidth=0.25
RoomDefinition "U_STM32MP25XXAI Power" [All] p0: scope1count=1 scope1_0_kind=ComponentClass scope1_0_value="U_STM32MP25XXAI Power" scope2count=1 scope2_0_kind=Board scope2_0_value=Board commentlength=0 region_x1=0 region_y1=0 region_x2=20000000 region_y2=10000000 confinementstyle=ConfineIn
RoomDefinition "U_STM32MP25XXAI I_Os" [All] p0: scope1count=1 scope1_0_kind=ComponentClass scope1_0_value="U_STM32MP25XXAI I_Os" scope2count=1 scope2_0_kind=Board scope2_0_value=Board commentlength=0 region_x1=0 region_y1=0 region_x2=20000000 region_y2=10000000 confinementstyle=ConfineIn
RoomDefinition U_PMIC [All] p0: scope1count=1 scope1_0_kind=ComponentClass scope1_0_value=U_PMIC scope2count=1 scope2_0_kind=Board scope2_0_value=Board commentlength=0 region_x1=0 region_y1=0 region_x2=20000000 region_y2=10000000 confinementstyle=ConfineIn
RoomDefinition U_eMMC [All] p0: scope1count=1 scope1_0_kind=ComponentClass scope1_0_value=U_eMMC scope2count=1 scope2_0_kind=Board scope2_0_value=Board commentlength=0 region_x1=0 region_y1=0 region_x2=20000000 region_y2=10000000 confinementstyle=ConfineIn
RoomDefinition U_2_DDR3L_16bits [All] p0: scope1count=1 scope1_0_kind=ComponentClass scope1_0_value=U_2_DDR3L_16bits scope2count=1 scope2_0_kind=Board scope2_0_value=Board commentlength=0 region_x1=0 region_y1=0 region_x2=20000000 region_y2=10000000 confinementstyle=ConfineIn
RoomDefinition "U_STM32MP25XXAI Power" [InComponentClass('U_STM32MP25XXAI Power')] p1: confinementstyle=ConfineIn formatcopy=TRUE lockcomponents=FALSE outline -226.399,-195.173 -175.599,-195.173 -175.599,-169.773 -226.399,-169.773
RoomDefinition "U_STM32MP25XXAI I_Os" [InComponentClass('U_STM32MP25XXAI I_Os')] p2: confinementstyle=ConfineIn formatcopy=TRUE lockcomponents=FALSE outline -226.399,-195.173 -175.599,-195.173 -175.599,-169.773 -226.399,-169.773
RoomDefinition U_PMIC [InComponentClass('U_PMIC')] p3: confinementstyle=ConfineIn formatcopy=TRUE lockcomponents=FALSE outline -226.399,-195.173 -175.599,-195.173 -175.599,-169.773 -226.399,-169.773
RoomDefinition U_eMMC [InComponentClass('U_eMMC')] p4: confinementstyle=ConfineIn formatcopy=TRUE lockcomponents=FALSE outline -226.399,-195.173 -175.599,-195.173 -175.599,-169.773 -226.399,-169.773
RoomDefinition U_2_DDR3L_16bits [InComponentClass('U_2_DDR3L_16bits')] p5: confinementstyle=ConfineIn formatcopy=TRUE lockcomponents=FALSE outline -226.399,-195.173 -175.599,-195.173 -175.599,-169.773 -226.399,-169.773
RoutingCorners [All] p0: scope1count=1 scope1_0_kind=Board scope1_0_value=Board scope2count=1 scope2_0_kind=Board scope2_0_value=Board commentlength=0 cornerstyle=45-Degree minsetback=2.54 maxsetback=2.54
RoutingLayers [All] p0: scope1count=1 scope1_0_kind=Board scope1_0_value=Board scope2count=1 scope2_0_kind=Board scope2_0_value=Board commentlength=0 top layer=Automatic mid layer 1=Automatic mid layer 2=Automatic mid layer 3=Automatic mid layer 4=Automatic bottom layer=Automatic
RoutingPriority [All] p0: scope1count=1 scope1_0_kind=Board scope1_0_value=Board scope2count=1 scope2_0_kind=Board scope2_0_value=Board commentlength=0
RoutingTopology [All] p0: scope1count=1 scope1_0_kind=Board scope1_0_value=Board scope2count=1 scope2_0_kind=Board scope2_0_value=Board commentlength=0 topology=Shortest
RoutingVias RoutingVias_Default [All] p0: scope1count=1 scope1_0_kind=Board scope1_0_value=Board scope2count=1 scope2_0_kind=Board scope2_0_value=Board commentlength=0 holewidth=0.15 width=0.4 viastyle="Through Hole" minholewidth=0.15 minwidth=0.4 maxholewidth=0.35 maxwidth=0.6
RoutingVias RoutingVias_Default [All] p1: holewidth=0.15 width=0.4 viastyle="Through Hole" minholewidth=0.15 minwidth=0.4 maxholewidth=0.35 maxwidth=0.6 viatemplateguid#1={BF886351-5902-4D8E-87A9-DD407FAE4AFA} viatemplateguid#2={A479BBDC-94B7-4D18-B59D-B7A18B767B5F} viatemplateguid#3={564DD7E2-F718-4BCE-8A99-5417C9FECCB6} viatemplateguid#4={FF627BA4-9930-4358-AE69-D745639122BF} viatemplateguid#5={3FF096CA-B7A5-4E0B-A50A-8B2CD18CCC19} viatemplatename#1=v50h25m30mx30 viatemplatename#2=v55h35m40mx40 viatemplatename#3=v40h20m0mx0 viatemplatename#4=v40h20m25mx25 viatemplatename#5=v50h25m0mx0
ShortCircuit ShortCircuit_Link200 [All] p0: scope1count=1 scope1_0_kind=PadClass scope1_0_value=PC_LINK200 scope2count=1 scope2_0_kind=Board scope2_0_value=Board commentlength=0 allowed=TRUE
ShortCircuit ShortCircuit_Link200 [InPadClass('PC_LINK200')] p1: allowed=TRUE
SilkToBoardRegionClearance [All] p0: scope1count=1 scope1_0_kind=Board scope1_0_value=Board scope2count=1 scope2_0_kind=Board scope2_0_value=Board commentlength=0
SilkToSilkClearance [All] p0: scope1count=1 scope1_0_kind=Board scope1_0_value=Board scope2count=1 scope2_0_kind=Board scope2_0_value=Board commentlength=0
SilkToSilkClearance [All] p1: silktosilkclearance=0.2
SilkToSolderMaskClearance [All] p0 off: scope1count=1 scope1_0_kind=Board scope1_0_value=Board scope2count=1 scope2_0_kind=Board scope2_0_value=Board commentlength=44 // Protel DXP Scope 1 Expression Was: IsPad
SilkToSolderMaskClearance [IsPad] p1: minsilkscreentomaskgap=0.015 clearancetoexposedcopper=TRUE
SolderMaskExpansion [All] p0: scope1count=1 scope1_0_kind=Board scope1_0_value=Board scope2count=1 scope2_0_kind=Board scope2_0_value=Board commentlength=0 expansion=0.1
SolderMaskExpansion [All] p1: expansion=0.1 istentingtop=FALSE
UnRoutedNet [All] p0: scope1count=1 scope1_0_kind=Board scope1_0_value=Board scope2count=1 scope2_0_kind=Board scope2_0_value=Board commentlength=0
UnpouredPolygon [All] p0: scope1count=1 scope1_0_kind=Board scope1_0_value=Board scope2count=1 scope2_0_kind=Board scope2_0_value=Board commentlength=0
ViasUnderSMD [All] p0: scope1count=1 scope1_0_kind=PadClass scope1_0_value=PC_VIAS-IN-PAD_OK scope2count=1 scope2_0_kind=Board scope2_0_value=Board commentlength=0 allowed=TRUE
ViasUnderSMD [InPadClass('PC_VIAS-IN-PAD_OK')] p1: allowed=TRUE
Width Width_Default [All] p0: scope1count=1 scope1_0_kind=NetClass scope1_0_value="All Nets" scope2count=1 scope2_0_kind=Board scope2_0_value=Board commentlength=0 maxlimit=10 minlimit=0.09 preferedwidth=0.09
Width Width_Default [InNetClass('All Nets')] p1: maxlimit=10 minlimit=0.09 preferedwidth=0.09
16 further rules are at their usual default settings.

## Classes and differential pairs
net class eMMC.SDMMC2_D[0..7]: eMMC.SDMMC2_D0 eMMC.SDMMC2_D1 eMMC.SDMMC2_D2 eMMC.SDMMC2_D3 eMMC.SDMMC2_D4 eMMC.SDMMC2_D5 eMMC.SDMMC2_D6 eMMC.SDMMC2_D7
component class "U_STM32MP25XXAI Power": C1 C2 C3 C4 C5 C6 C7 C8 C9 C10 C11 C12 C13 C14 C15 C16 C17 C25 C31 C44 C45 C46 C47 C52 C53 C54 C55 C56 C57 C58 C59 C60 C61 C62 C63 C64 C65 C66 C67 C68 C69 C70 C71 C72 C73 C74 C75 C79 C87 C88 C89 C96 C97 C98 C212 C234 C275 C285 CN12 D6 R66 R67 R249 R267 R269 R286
component class "U_STM32MP25XXAI I_Os": C33 C81 C86 C90 C92 R27 R64 R75 R260 R261 R272 U27 X1 X2
component class U_PMIC: B2 C18 C19 C20 C21 C22 C23 C24 C26 C27 C28 C29 C30 C32 C34 C35 C36 C37 C38 C39 C40 C41 C42 C43 C91 C141 C142 C152 C153 C154 C155 C156 C157 C183 C184 C186 C187 C188 C189 C190 C193 C199 C200 C202 C204 C206 C207 C208 C209 C217 L1 L2 L3 L4 L5 L6 L7 LD11 LNK1 LNK2 LNK4 LNK7 LNK8 LNK11 R2 R46 R57 R59 R60 R81 R210
component class U_eMMC: C177 C178 C179 C180 C181 C182 D5 R37 R44 R49 R248 TP9 U24
component class U_2_DDR3L_16bits: C48 C76 C77 C80 C130 C131 C132 C133 C134 C140 C143 C146 C147 C148 C149 C159 C172 C173 C185 C191 C192 C194 C201 C205 C302 C304 C306 C307 C360 C361 C362 C363 C364 C367 C373 C374 C375 C384 C390 C399 R68 R83 R148 R149 R150 R151 R152 R153 R154 R155 R156 R158 R159 R160 R163 R166 R167 R168 R170 R171 R172 R173 R174 R175 R176 R177 R178 R179 R180 R262 U14 U16
differential pair DDR_DQS3: +DDR_DQS3_P -DDR_DQS3_N
differential pair DDR_DQS2: +DDR_DQS2_P -DDR_DQS2_N
differential pair DDR_DQS1: +DDR_DQS1_P -DDR_DQS1_N
differential pair DDR_DQS0: +DDR_DQS0_P -DDR_DQS0_N
differential pair " ": +DDR_CLK_P -DDR_CLK_N

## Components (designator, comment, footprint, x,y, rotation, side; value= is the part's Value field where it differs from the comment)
B2 "SW_PUSH_SMD_2P" SWI_WE_434121025816 36.59,67.295 r0 top
C1 "Capacitor" C0201_MURATA_GRM033_H0P3 92.825,72.825 r0 bottom
C2 "Capacitor" C0201_MURATA_GRM033_H0P3 93.601,73.65 r180 bottom
C3 "Capacitor" C0201_MURATA_GRM033_H0P3 91.825,73.65 r180 bottom
C4 "Capacitor" C0201_MURATA_GRM033_H0P3 92.55,75.25 r0 bottom
C5 "Capacitor" C0201_MURATA_GRM033_H0P3 92.826,74.475 r180 bottom
C6 "Capacitor" C0201_MURATA_GRM033_H0P3 91.2,74.525 r270 bottom
C7 "Capacitor" C0201_MURATA_GRM033_H0P3 94.4,72 r0 bottom
C8 "Capacitor" C0201_MURATA_GRM033_H0P3 94.425,70.425 r180 bottom
C9 "Capacitor" C0201_MURATA_GRM033_H0P3 93.3,72 r180 bottom
C10 "Capacitor" C0201_MURATA_GRM033_H0P3 92.675,70.48 r0 bottom
C11 "Capacitor" C0201_MURATA_GRM033_H0P3 95.25,70.175 r270 bottom
C12 "Capacitor" C0201_MURATA_GRM033_H0P3 94.425,69.575 r180 bottom
C13 "Capacitor" C0201_MURATA_GRM033_H0P3 95.232,73.625 r0 bottom
C14 "Capacitor" C0201_MURATA_GRM033_H0P3 94.425,74.48 r180 bottom
C15 "Capacitor" C0201_MURATA_GRM033_H0P3 96.175,74.475 r180 bottom
C16 "Capacitor" C0201_MURATA_GRM033_H0P3 96.075,75.6 r90 bottom
C17 "Capacitor" C0201_MURATA_GRM033_H0P3 94.05,75.875 r0 bottom
C18 "Cap_POL_TANA" CPOL_TCJ-B_1210_H210 40.812,72.961 r180 top
C19 "Capacitor" C0805 71.6,72.25 r270 top
C20 "Capacitor" C0603 52.6,72.325 r270 top
C21 "Capacitor" C0805 50.5,71.173 r270 top
C22 "Capacitor" C0603 71.275,85.075 r270 top
C23 "Capacitor" C0603 70,85.075 r270 top
C24 "Capacitor" C0603 68.725,85.075 r270 top
C25 "Capacitor" C0201_MURATA_GRM033_H0P3 93.75,75.25 r0 bottom
C26 "Capacitor" C0603 53.8,84.225 r270 top
C27 "Capacitor" C0603 51.2,84.225 r270 top
C28 "Capacitor" C0603 52.5,84.225 r270 top
C29 "Capacitor" C0603 55.525,81.725 r270 top
C30 "Capacitor" C0603 57.75,81.075 r0 top
C31 "Capacitor" C0201_MURATA_GRM033_H0P3 94.4,72.775 r180 bottom
C32 "Capacitor" C0603 66.125,80.225 r180 top
C33 "Capacitor" C0402 75.425,69.325 r90 top
C34 "Capacitor" C0603 71.5,79.1 r270 top
C35 "Capacitor" C0603 72.8,79.1 r270 top
C36 "Capacitor" C0603 70.2,79.1 r270 top
C37 "Capacitor" C0603 68.9,79.1 r270 top
C38 "Capacitor" C0603 66.075,78.575 r180 top
C39 "Capacitor" C0402 52.945,78.575 r0 top
C40 "Capacitor" C0402 52.945,77.75 r0 top
C41 "Capacitor" C0603 46.775,75.75 r0 top
C42 "Cap_POL_TANA" CPOL_TCJ-B_1210_H210 40.812,76.523 r180 top
C43 "Capacitor" C0402 50.035,76.8 r0 top
C44 "Capacitor" C0201_MURATA_GRM033_H0P3 91.2,69.6 r180 bottom
C45 "Capacitor" C0201_MURATA_GRM033_H0P3 92.8,69.6 r0 bottom
C46 "Capacitor" C0201_MURATA_GRM033_H0P3 92.025,72 r270 bottom
C47 "Capacitor" C0201_MURATA_GRM033_H0P3 91.2,70.388 r180 bottom
C48 "Capacitor" C0402 123.6,77.25 r180 top locked
C52 "Capacitor" C0201_MURATA_GRM033_H0P3 91.2,71.2 r0 bottom
C53 "Capacitor" C0201_MURATA_GRM033_H0P3 97.45,69.675 r270 bottom
C54 "Capacitor" C0201_MURATA_GRM033_H0P3 96.35,70.6 r180 bottom
C55 "Capacitor" C0201_MURATA_GRM033_H0P3 96.375,71.275 r180 bottom
C56 "Capacitor" C0201_MURATA_GRM033_H0P3 96.349,72.875 r180 bottom
C57 "Capacitor" C0201_MURATA_GRM033_H0P3 96.301,71.974 r0 bottom
C58 "Capacitor" C0201_MURATA_GRM033_H0P3 97.5,72.925 r90 bottom
C59 "Capacitor" C0201_MURATA_GRM033_H0P3 96.1,69.45 r90 bottom
C60 "Capacitor" C0201_MURATA_GRM033_H0P3 96.356,73.524 r0 bottom
C61 "Capacitor" C0201_H0P5 90.317,71.988 r90 bottom
C62 "Capacitor" C0201_MURATA_GRM033_H0P3 97.3,65.575 r270 bottom
C63 "Capacitor" C0201_MURATA_GRM033_H0P3 99.775,64.675 r180 bottom
C64 "Capacitor" C0201_MURATA_GRM033_H0P3 99.775,65.675 r180 bottom
C65 "Capacitor" C0201_MURATA_GRM033_H0P3 99.65,66.325 r180 bottom
C66 "Capacitor" C0201_MURATA_GRM033_H0P3 90.7,77.475 r180 bottom
C67 "Capacitor" C0201_MURATA_GRM033_H0P3 87.63,65.845 r270 bottom
C68 "Capacitor" C0201_MURATA_GRM033_H0P3 88.375,66.125 r270 bottom
C69 "Capacitor" C0201_MURATA_GRM033_H0P3 90.48,75.97 r0 bottom
C70 "Capacitor" C0201_MURATA_GRM033_H0P3 87.8,78.375 r90 bottom
C71 "Capacitor" C0201_MURATA_GRM033_H0P3 93.201,76.675 r90 bottom
C72 "Capacitor" C0201_MURATA_GRM033_H0P3 91.675,77.975 r270 bottom
C73 "Capacitor" C0201_MURATA_GRM033_H0P3 90.85,76.925 r0 bottom
C74 "Capacitor" C0201_MURATA_GRM033_H0P3 90.5,74.775 r90 bottom
C75 "Capacitor" C0201_MURATA_GRM033_H0P3 87.65,69.425 r0 bottom
C76 "Capacitor" C0402 121.225,59.525 r180 top
C77 "Capacitor" C0402 106.775,59.35 r180 top locked
C79 "Capacitor" C0201_H0P5 88.6,70.125 r180 bottom
C80 "Capacitor" C0603 121.275,58.5 r180 top
C81 "Capacitor" C0402 77.85,67.85 r90 top
C86 "Capacitor" C0402 77.85,65.45 r270 top
C87 "" C0402 74.05,64.575 r90 top
C88 "Capacitor" C0402 67.475,60.85 r270 top
C89 "Capacitor" C0201_MURATA_GRM033_H0P3 97.075,67.825 r0 bottom
C90 "Capacitor" C0402 77.65,62.15 r270 top
C91 "Capacitor" C0402 60.345,67.16 r270 top
C92 "Capacitor" C0402 75.075,59.825 r180 top
C96 "Capacitor" C0201_MURATA_GRM033_H0P3 98.85,65.275 r90 bottom
C97 "Capacitor" C0201_MURATA_GRM033_H0P3 91.15,79.375 r180 bottom
C98 "Capacitor" C0201_MURATA_GRM033_H0P3 86.9,79.175 r0 bottom
C130 "Capacitor" C0603 135.55,79.025 r270 bottom locked
C131 "Capacitor" C0402 133.775,79.25 r270 bottom locked
C132 "Capacitor" C0402 131.9,79.25 r270 bottom locked
C133 "Capacitor" C0402 129.95,79.25 r270 bottom locked
C134 "Capacitor" C0402 128.075,79.25 r270 bottom locked
C140 "Capacitor" C0603 125.825,76.8 r0 bottom locked
C141 "Capacitor" C0402 59.1,67.75 r270 top
C142 "Capacitor" C0402 58.275,68.06 r270 top
C143 "Capacitor" C0402 127.35,75.75 r0 bottom locked
C146 "Capacitor" C0402 135.075,75.6 r180 bottom locked
C147 "Capacitor" C0402 133.3,75.55 r180 bottom locked
C148 "Capacitor" C0402 138.45,75.4 r0 bottom locked
C149 "Capacitor" C0402 136.775,75.4 r0 bottom locked
C152 "Capacitor" C0805 59.5,85.8 r270 top
C153 "Capacitor" C0402 59.675,69.72 r90 top
C154 "Capacitor" C0402 57,68.725 r90 top
C155 "Capacitor" C0402 56.227,67.695 r90 top
C156 "Capacitor" C0402 63.125,71.02 r90 top
C157 "Capacitor" C0805 57.65,85.8 r270 top
C159 "Capacitor" C0402 140.825,73.5 r180 bottom locked
C172 "Capacitor" C0402 140.825,71.775 r180 bottom locked
C173 "Capacitor" C0603 111.175,70.925 r0 bottom locked
C177 "Capacitor" C0402 110.8,92.025 r0 bottom
C178 "Capacitor" C0402 113.275,90 r270 bottom
C179 "Capacitor" C0402 115.225,88.475 r270 bottom
C180 "Capacitor" C0402 108.85,88.475 r0 bottom
C181 "Capacitor" C0402 106.7,86.35 r90 bottom
C182 "Capacitor" C0402 107.825,86.35 r90 bottom
C183 "Capacitor" C0603 67.45,85.075 r270 top
C184 "Capacitor" C0603 66.497,74.625 r180 top
C185 "Capacitor" C0402 140.825,69.7 r180 bottom locked
C186 "Capacitor" C0805 73.4,72.25 r270 top
C187 "Capacitor" C0805 69.8,72.25 r270 top
C188 "Capacitor" C0402 65.525,69.04 r90 top
C189 "Capacitor" C0402 64.7,69.04 r90 top
C190 "Capacitor" C0402 66.75,69.515 r270 top
C191 "Capacitor" C0402 120.425,69.15 r0 bottom locked
C192 "Capacitor" C0402 116.7,68.7 r90 bottom locked
C193 "Capacitor" C0805 55.8,85.8 r270 top
C194 "Capacitor" C0402 121.975,66.55 r180 bottom
C199 "Capacitor" C0603 53.675,74.6 r90 top
C200 "Capacitor" C0603 46.775,77.05 r0 top
C201 "Capacitor" C0402 136.8,64.4 r90 bottom locked
C202 "Capacitor" C0603 46.775,74.45 r0 top
C204 "Capacitor" C0805 48.7,71.173 r270 top
C205 "Capacitor" C0402 131.15,62.775 r90 bottom locked
C206 "Capacitor" C0805 45.1,71.173 r270 top
C207 "Capacitor" C0805 46.9,71.173 r270 top
C208 "Capacitor" C0402 61.17,67.16 r270 top
C209 "Capacitor" C0402 61.85,68.87 r90 top
C212 "Capacitor" C0201_MURATA_GRM033_H0P3 91.585,73.1 r180 bottom
C217 "Capacitor" C0402 56.225,69.87 r270 top
C234 "Capacitor" C0201_MURATA_GRM033_H0P3 90.275,70.01 r270 bottom
C275 "Capacitor" C0201_MURATA_GRM033_H0P3 88.35,77.2 r0 bottom
C285 "Capacitor" C0201_MURATA_GRM033_H0P3 97.28,74.91 r0 bottom
C302 "Capacitor" C0402 135,64.4 r90 bottom locked
C304 "Capacitor" C0402 133.05,62.775 r90 bottom locked
C306 "Capacitor" C0402 129.25,62.775 r90 bottom locked
C307 "Capacitor" C0402 127.325,62.775 r90 bottom locked
C360 "Capacitor" C0402 127.125,65.75 r0 top
C361 "Capacitor" C0402 128.75,65.75 r0 top
C362 "Capacitor" C0402 130.375,65.75 r180 top
C363 "Capacitor" C0402 138.075,65.75 r180 top
C364 "Capacitor" C0603 138.075,64.725 r180 top
C367 "Capacitor" C0402 133.4,81 r180 top
C373 "Capacitor" C0402 110.775,59.525 r0 top
C374 "Capacitor" C0402 112.375,59.525 r0 top
C375 "Capacitor" C0402 113.975,59.525 r180 top
C384 "Capacitor" C0402 111,69.75 r0 bottom locked
C390 "Capacitor" C0402 122.05,69.15 r0 bottom
C399 "Capacitor" C0603 138.175,64.725 r90 bottom locked
CN12 "" CON_MOLEX_53047-0210 67.475,64.05 r270 top
D5 "BAT60JFILM" DIO_SOD323 104.175,89.7 r90 bottom
D6 "DIODE_3P_DUAL_COMMON_CATHODE" DIO_SOT23 71.725,64.025 r270 top
L1 "Inductor" IND_2016_MURATA_LQM2MPN2R2NG0 58.295,83.175 r180 top
L2 "Inductor" IND_2520_TOKO_DFE252012P 66.415,82.45 r0 top
L3 "Inductor" IND_2016_MURATA_LQM2MPN2R2NG0 53.35,81.075 r90 top
L4 "Inductor" IND_2520_TOKO_DFE252012P 67.925,76.6 r0 top
L5 "Inductor" IND_2016_MURATA_LQM2MPN2R2NG0 50.525,74.7 r180 top
L6 "Inductor" IND_2016_MURATA_LQM2MPN2R2NG0 67,72 r0 top
L7 "Inductor" IND_2016_MURATA_LQM2MPN2R2NG0 52.9,70.05 r180 top
LD11 "LED_green" LED_0603_OSRAM_LG-Q396-PS-35_GREEN_1A2K_H0P4 42.887,67.327 r270 top
LNK1 "link_200" LINK200#1 60.6,84.123 r0 top
LNK2 "link_200" LINK200#2 76.219,76.687 r90 top
LNK4 "link_200" LINK200#2 50.35,81.125 r180 top
LNK7 "link_200" LINK200#2 72.45,75.35 r270 top
LNK8 "link_200" LINK200#2 48.2,77.498 r0 top
LNK11 "link_200" LINK200#2 74.6,71.44 r180 top
R2 "" R0402 55.08,67.695 r90 top
R27 "Resistor" R0402 73.125,66.475 r90 top
R37 "Resistor" R0402 102.975,91.05 r90 top
R44 "Resistor" R0402 103.1,85.978 r270 top
R46 "" R0402 62.65,81.998 r270 top
R49 "Resistor" R0402 114.175,83.685 r0 top
R57 "" R0402 63.35,67.95 r90 top
R59 "" R0402 52.98,67.695 r90 top
R60 "" R0402 54.03,67.695 r90 top
R64 "" R0402 79.15,67.45 r180 top
R66 "Resistor" R0402 68.675,60.845 r270 top
R67 "Resistor" R0402 71.075,66.375 r0 top
R68 "Resistor" R0402 133.625,65.675 r180 top
R75 "" R0402 76.925,59.725 r0 top
R81 "" R0402 62.663,84.348 r270 top
R83 "Resistor" R0402 115.575,59.45 r0 top
R148 "Resistor" R0402 134.225,77.425 r90 bottom locked
R149 "Resistor" R0402 133.275,77.425 r90 bottom locked
R150 "Resistor" R0402 132.325,77.425 r90 bottom locked
R151 "Resistor" R0402 131.375,77.425 r90 bottom locked
R152 "Resistor" R0402 130.425,77.425 r90 bottom locked
R153 "Resistor" R0402 129.475,77.425 r90 bottom locked
R154 "Resistor" R0402 128.525,77.425 r90 bottom
R155 "Resistor" R0402 127.575,77.425 r90 bottom locked
R156 "Resistor" R0402 123.75,75.525 r270 bottom locked
R158 "Resistor" R0402 139.025,73.95 r0 bottom locked
R159 "Resistor" R0402 139.025,73 r0 bottom locked
R160 "Resistor" R0402 139.025,72.05 r0 bottom locked
R163 "Resistor" R0402 139.025,71.1 r0 bottom locked
R166 "Resistor" R0402 139.025,70.15 r0 bottom locked
R167 "Resistor" R0402 133.6,69.375 r90 bottom locked
R168 "Resistor" R0402 138.375,69.2 r0 bottom locked
R170 "Resistor" R0402 136.35,66.3 r270 bottom locked
R171 "Resistor" R0402 135.4,66.3 r270 bottom locked
R172 "Resistor" R0402 134.45,66.3 r270 bottom locked
R173 "Resistor" R0402 133.5,66.3 r270 bottom locked
R174 "Resistor" R0402 132.55,64.775 r270 bottom locked
R175 "Resistor" R0402 131.6,64.775 r270 bottom locked
R176 "Resistor" R0402 130.65,64.775 r270 bottom locked
R177 "Resistor" R0402 129.7,64.775 r270 bottom locked
R178 "Resistor" R0402 128.75,64.775 r270 bottom locked
R179 "Resistor" R0402 127.8,64.775 r270 bottom locked
R180 "Resistor" R0402 126.85,64.775 r270 bottom
R210 "Resistor" R0402 42.887,69.52 r270 top
R248 "Resistor" R0402 111.225,87.95 r0 bottom
R249 "Resistor" R0603 75.65,75.25 r270 top
R260 "Resistor" R0402 60.33,82.13 r270 bottom
R261 "Resistor" R0402 61.305,82.13 r270 bottom
R262 "Resistor" R0201_H0P23 97.624,74.149 r0 bottom
R267 "" R0402 86.8,70.375 r180 bottom
R269 "" R0402 86.304,69.315 r0 bottom
R272 "Resistor" R0402 53.475,65.879 r0 bottom
R286 "" R0402 97.725,64.025 r90 bottom
TP9 "Test Point" TP_SMD_1MM 112.43,83.629 r90 top
U14 "NT5CC256M16ER-EK" ICC_VFBGA96_9x13_P080 133.175,70.95 r270 top locked
U16 "NT5CC256M16ER-EK" ICC_VFBGA96_9x13_P080 116.7,64.725 r270 top locked
U24 "eMMC_THGBMTG5D1LBAIL" ICC_P-WFBGA153_13X11P5_P050 110.525,90.6 r0 top locked
U26 "STPMIC25APQR" ICC_QFN56-EPAD_6P5X6P5_P040 60,75.8 r90 top
U27 "STM32MP257FAI3" ICC_LFBGA436_18X18_P080_H1P70_STM32MP257_CODE-B0D1 94,72.4 r0 top locked
X1 "XTAL_2_PINS" CRY_NX2012SA_2P 76.525,66.65 r270 top
X2 "XTAL_4_PINS" CRY_NX1612SA_4P 76.098,61.176 r180 top

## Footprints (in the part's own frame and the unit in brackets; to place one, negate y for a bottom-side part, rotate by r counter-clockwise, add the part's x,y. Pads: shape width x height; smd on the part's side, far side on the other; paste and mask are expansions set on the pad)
C0201_H0P5 [mm] "MCD-01534"
  rect 0.4x0.5 smd mask+0: 1(-0.3,0) 2(0.3,0)
C0201_MURATA_GRM033_H0P3 [mm] "GRM033R60J105ME11"
  rect 0.35x0.35 smd mask+0: 1(-0.275,0) 2(0.275,0)
C0402 [mm]
  rect 0.51x0.56 smd mask+0: 1(-0.45,0) 2(0.45,0)
C0603 [mm]
  rect 0.64x0.89 smd mask+0: 1(-0.7,0) 2(0.7,0)
  silkscreen extent -1.05,-0.55 1.02,0.55
C0805 [mm]
  rect 0.9x1.4 smd mask+0: 1(-0.85,0) 2(0.85,0)
  silkscreen extent -1.3,-0.77 1.3,0.77
CON_MOLEX_53047-0210 [mm]
  oval 1x1.3 hole 0.5 mask+0: 1(-0.625,0) 2(0.625,0)
  silkscreen extent -2.12,-1.15 2.13,2.05
CPOL_TCJ-B_1210_H210 [mm] "MCD-01791"
  rect 1.35x2.8 smd mask+0: 1(-1.375,0) 2(1.375,0)
  silkscreen extent -2.33,-1.68 1.85,1.68
CRY_NX1612SA_4P [mm] "MCD-02262"
  rect 0.75x0.6 smd mask+0: 1(-0.525,-0.375) 2(0.525,-0.375) 3(0.525,0.375) 4(-0.525,0.375)
  silkscreen extent -1.02,-0.8 0.03,0.6
CRY_NX2012SA_2P [mm]
  rect 1x1.25 smd mask+0: 1(-0.75,0) 2(0.75,0)
  silkscreen extent -1.05,-0.75 1.05,0.75
DIO_SOD323 [mm]
  rect 1.06x0.54 smd mask+0: 1(-1.07,0) 2(1.07,0)
  silkscreen extent -0.9,-0.72 0.9,0.72
DIO_SOT23 [mm]
  rect 1x1.4 smd mask+0: 1(-0.95,-1.1) 2(0.95,-1.1) 3(0,1.1)
  silkscreen extent -1.63,-0.82 1.63,0.82
ICC_LFBGA436_18X18_P080_H1P70_STM32MP257_CODE-B0D1 [mm] "MCD02000"
  round 0.3 smd paste+0.025 mask+0: A1(-8.4,8.4) A2(-7.6,8.4) A3(-6.8,8.4) A4(-6,8.4) A7(-3.6,8.4) A8(-2.8,8.4) A11(-0.4,8.4) A12(0.4,8.4) A15(2.8,8.4) A16(3.6,8.4) A19(6,8.4) A20(6.8,8.4) A21(7.6,8.4) A22(8.4,8.4) AA1(-8.4,-7.6) AA2(-7.6,-7.6) AA3(-6.8,-7.6) AA4(-6,-7.6) AA6(-4.4,-7.6) AA7(-3.6,-7.6) AA8(-2.8,-7.6) AA10(-1.2,-7.6) AA11(-0.4,-7.6) AA12(0.4,-7.6) AA14(2,-7.6) AA15(2.8,-7.6) AA16(3.6,-7.6) AA18(5.2,-7.6) AA19(6,-7.6) AA20(6.8,-7.6) AA21(7.6,-7.6) AA22(8.4,-7.6) AB1(-8.4,-8.4) AB2(-7.6,-8.4) AB3(-6.8,-8.4) AB4(-6,-8.4) AB7(-3.6,-8.4) AB8(-2.8,-8.4) AB11(-0.4,-8.4) AB12(0.4,-8.4) AB15(2.8,-8.4) AB16(3.6,-8.4) AB19(6,-8.4) AB20(6.8,-8.4) AB21(7.6,-8.4) AB22(8.4,-8.4) B1(-8.4,7.6) B2(-7.6,7.6) B3(-6.8,7.6) B4(-6,7.6) B5(-5.2,7.6) B7(-3.6,7.6) B8(-2.8,7.6) B9(-2,7.6) B11(-0.4,7.6) B12(0.4,7.6) B13(1.2,7.6) B15(2.8,7.6) B16(3.6,7.6) B17(4.4,7.6) B19(6,7.6) B20(6.8,7.6) B21(7.6,7.6) B22(8.4,7.6) C1(-8.4,6.8) C2(-7.6,6.8) C3(-6.8,6.8) C4(-6,6.8) C5(-5.2,6.8) C6(-4.4,6.8) C7(-3.6,6.8) C8(-2.8,6.8) C9(-2,6.8) C10(-1.2,6.8) C11(-0.4,6.8) C12(0.4,6.8) C13(1.2,6.8) C14(2,6.8) C15(2.8,6.8) C16(3.6,6.8) C17(4.4,6.8) C18(5.2,6.8) C19(6,6.8) C20(6.8,6.8) C21(7.6,6.8) C22(8.4,6.8) D1(-8.4,6) D2(-7.6,6) D3(-6.8,6) D4(-6,6) D5(-5.2,6) D6(-4.4,6) D7(-3.6,6) D8(-2.8,6) D9(-2,6) D10(-1.2,6) D11(-0.4,6) D12(0.4,6) D13(1.2,6) D14(2,6) D15(2.8,6) D16(3.6,6) D17(4.4,6) D18(5.2,6) D19(6,6) D20(6.8,6) D21(7.6,6) D22(8.4,6) E3(-6.8,5.2) E4(-6,5.2) E5(-5.2,5.2) E6(-4.4,5.2) E7(-3.6,5.2) E8(-2.8,5.2) E9(-2,5.2) E10(-1.2,5.2) E11(-0.4,5.2) E12(0.4,5.2) E13(1.2,5.2) E14(2,5.2) E15(2.8,5.2) E16(3.6,5.2) E17(4.4,5.2) E18(5.2,5.2) E19(6,5.2) E20(6.8,5.2) E21(7.6,5.2) F2(-7.6,4.4) F3(-6.8,4.4) F4(-6,4.4) F5(-5.2,4.4) F6(-4.4,4.4) F7(-3.6,4.4) F8(-2.8,4.4) F9(-2,4.4) F10(-1.2,4.4) F11(-0.4,4.4) F12(0.4,4.4) F13(1.2,4.4) F14(2,4.4) F15(2.8,4.4) F16(3.6,4.4) F17(4.4,4.4) F18(5.2,4.4) F19(6,4.4) F20(6.8,4.4) G1(-8.4,3.6) G2(-7.6,3.6) G3(-6.8,3.6) G4(-6,3.6) G5(-5.2,3.6) G6(-4.4,3.6) G7(-3.6,3.6) G8(-2.8,3.6) G9(-2,3.6) G10(-1.2,3.6) G11(-0.4,3.6) G12(0.4,3.6) G13(1.2,3.6) G14(2,3.6) G15(2.8,3.6) G16(3.6,3.6) G17(4.4,3.6) G18(5.2,3.6) G19(6,3.6) G20(6.8,3.6) G21(7.6,3.6) G22(8.4,3.6) H1(-8.4,2.8) H2(-7.6,2.8) H3(-6.8,2.8) H4(-6,2.8) H5(-5.2,2.8) H6(-4.4,2.8) H7(-3.6,2.8) H8(-2.8,2.8) H9(-2,2.8) H10(-1.2,2.8) H11(-0.4,2.8) H12(0.4,2.8) H13(1.2,2.8) H14(2,2.8) H15(2.8,2.8) H16(3.6,2.8) H17(4.4,2.8) H18(5.2,2.8) H19(6,2.8) H20(6.8,2.8) H21(7.6,2.8) H22(8.4,2.8) J3(-6.8,2) J4(-6,2) J5(-5.2,2) J6(-4.4,2) J7(-3.6,2) J8(-2.8,2) J9(-2,2) J10(-1.2,2) J11(-0.4,2) J12(0.4,2) J13(1.2,2) J14(2,2) J15(2.8,2) J16(3.6,2) J17(4.4,2) J18(5.2,2) J19(6,2) J20(6.8,2) J21(7.6,2) K2(-7.6,1.2) K3(-6.8,1.2) K4(-6,1.2) K5(-5.2,1.2) K6(-4.4,1.2) K7(-3.6,1.2) K8(-2.8,1.2) K9(-2,1.2) K10(-1.2,1.2) K11(-0.4,1.2) K12(0.4,1.2) K13(1.2,1.2) K14(2,1.2) K15(2.8,1.2) K16(3.6,1.2) K17(4.4,1.2) K18(5.2,1.2) K19(6,1.2) K20(6.8,1.2) L1(-8.4,0.4) L2(-7.6,0.4) L3(-6.8,0.4) L4(-6,0.4) L5(-5.2,0.4) L6(-4.4,0.4) L7(-3.6,0.4) L8(-2.8,0.4) L9(-2,0.4) L10(-1.2,0.4) L11(-0.4,0.4) L12(0.4,0.4) L13(1.2,0.4) L14(2,0.4) L15(2.8,0.4) L16(3.6,0.4) L17(4.4,0.4) L18(5.2,0.4) L19(6,0.4) L20(6.8,0.4) L21(7.6,0.4) L22(8.4,0.4) M1(-8.4,-0.4) M2(-7.6,-0.4) M3(-6.8,-0.4) M4(-6,-0.4) M5(-5.2,-0.4) M6(-4.4,-0.4) M7(-3.6,-0.4) M8(-2.8,-0.4) M9(-2,-0.4) M10(-1.2,-0.4) M11(-0.4,-0.4) M12(0.4,-0.4) M13(1.2,-0.4) M14(2,-0.4) M15(2.8,-0.4) M16(3.6,-0.4) M17(4.4,-0.4) M18(5.2,-0.4) M19(6,-0.4) M20(6.8,-0.4) M21(7.6,-0.4) M22(8.4,-0.4) N3(-6.8,-1.2) N4(-6,-1.2) N5(-5.2,-1.2) N6(-4.4,-1.2) N7(-3.6,-1.2) N8(-2.8,-1.2) N9(-2,-1.2) N10(-1.2,-1.2) N11(-0.4,-1.2) N12(0.4,-1.2) N13(1.2,-1.2) N14(2,-1.2) N15(2.8,-1.2) N16(3.6,-1.2) N17(4.4,-1.2) N18(5.2,-1.2) N19(6,-1.2) N20(6.8,-1.2) N21(7.6,-1.2) P2(-7.6,-2) P3(-6.8,-2) P4(-6,-2) P5(-5.2,-2) P6(-4.4,-2) P7(-3.6,-2) P8(-2.8,-2) P9(-2,-2) P10(-1.2,-2) P11(-0.4,-2) P12(0.4,-2) P13(1.2,-2) P14(2,-2) P15(2.8,-2) P16(3.6,-2) P17(4.4,-2) P18(5.2,-2) P19(6,-2) P20(6.8,-2) R1(-8.4,-2.8) R2(-7.6,-2.8) R3(-6.8,-2.8) R4(-6,-2.8) R5(-5.2,-2.8) R6(-4.4,-2.8) R7(-3.6,-2.8) R8(-2.8,-2.8) R9(-2,-2.8) R10(-1.2,-2.8) R11(-0.4,-2.8) R12(0.4,-2.8) R13(1.2,-2.8) R14(2,-2.8) R15(2.8,-2.8) R16(3.6,-2.8) R17(4.4,-2.8) R18(5.2,-2.8) R19(6,-2.8) R20(6.8,-2.8) R21(7.6,-2.8) R22(8.4,-2.8) T1(-8.4,-3.6) T2(-7.6,-3.6) T3(-6.8,-3.6) T4(-6,-3.6) T5(-5.2,-3.6) T6(-4.4,-3.6) T7(-3.6,-3.6) T8(-2.8,-3.6) T9(-2,-3.6) T10(-1.2,-3.6) T11(-0.4,-3.6) T12(0.4,-3.6) T13(1.2,-3.6) T14(2,-3.6) T15(2.8,-3.6) T16(3.6,-3.6) T17(4.4,-3.6) T18(5.2,-3.6) T19(6,-3.6) T20(6.8,-3.6) T21(7.6,-3.6) T22(8.4,-3.6) U3(-6.8,-4.4) U4(-6,-4.4) U5(-5.2,-4.4) U6(-4.4,-4.4) U7(-3.6,-4.4) U8(-2.8,-4.4) U9(-2,-4.4) U10(-1.2,-4.4) U11(-0.4,-4.4) U12(0.4,-4.4) U13(1.2,-4.4) U14(2,-4.4) U15(2.8,-4.4) U16(3.6,-4.4) U17(4.4,-4.4) U18(5.2,-4.4) U19(6,-4.4) U20(6.8,-4.4) U21(7.6,-4.4) V2(-7.6,-5.2) V3(-6.8,-5.2) V4(-6,-5.2) V5(-5.2,-5.2) V6(-4.4,-5.2) V7(-3.6,-5.2) V8(-2.8,-5.2) V9(-2,-5.2) V10(-1.2,-5.2) V11(-0.4,-5.2) V12(0.4,-5.2) V13(1.2,-5.2) V14(2,-5.2) V15(2.8,-5.2) V16(3.6,-5.2) V17(4.4,-5.2) V18(5.2,-5.2) V19(6,-5.2) V20(6.8,-5.2) W1(-8.4,-6) W2(-7.6,-6) W3(-6.8,-6) W4(-6,-6) W5(-5.2,-6) W6(-4.4,-6) W7(-3.6,-6) W8(-2.8,-6) W9(-2,-6) W10(-1.2,-6) W11(-0.4,-6) W12(0.4,-6) W13(1.2,-6) W14(2,-6) W15(2.8,-6) W16(3.6,-6) W17(4.4,-6) W18(5.2,-6) W19(6,-6) W20(6.8,-6) W21(7.6,-6) W22(8.4,-6) Y1(-8.4,-6.8) Y2(-7.6,-6.8) Y3(-6.8,-6.8) Y4(-6,-6.8) Y5(-5.2,-6.8) Y6(-4.4,-6.8) Y7(-3.6,-6.8) Y8(-2.8,-6.8) Y9(-2,-6.8) Y10(-1.2,-6.8) Y11(-0.4,-6.8) Y12(0.4,-6.8) Y13(1.2,-6.8) Y14(2,-6.8) Y15(2.8,-6.8) Y16(3.6,-6.8) Y17(4.4,-6.8) Y18(5.2,-6.8) Y19(6,-6.8) Y20(6.8,-6.8) Y21(7.6,-6.8) Y22(8.4,-6.8)
  silkscreen extent -9.25,-9.1 9.1,9.25
ICC_P-WFBGA153_13X11P5_P050 [mm]
  round 0.23 smd mask+0: A1(-3.25,-3.25) A2(-3.25,-2.75) A3(-3.25,-2.25) A4(-3.25,-1.75) A5(-3.25,-1.25) A6(-3.25,-0.75) A7(-3.25,-0.25) A8(-3.25,0.25) A9(-3.25,0.75) A10(-3.25,1.25) A11(-3.25,1.75) A12(-3.25,2.25) A13(-3.25,2.75) A14(-3.25,3.25) B1(-2.75,-3.25) B2(-2.75,-2.75) B3(-2.75,-2.25) B4(-2.75,-1.75) B5(-2.75,-1.25) B6(-2.75,-0.75) B7(-2.75,-0.25) B8(-2.75,0.25) B9(-2.75,0.75) B10(-2.75,1.25) B11(-2.75,1.75) B12(-2.75,2.25) B13(-2.75,2.75) B14(-2.75,3.25) C1(-2.25,-3.25) C2(-2.25,-2.75) C3(-2.25,-2.25) C4(-2.25,-1.75) C5(-2.25,-1.25) C6(-2.25,-0.75) C7(-2.25,-0.25) C8(-2.25,0.25) C9(-2.25,0.75) C10(-2.25,1.25) C11(-2.25,1.75) C12(-2.25,2.25) C13(-2.25,2.75) C14(-2.25,3.25) D1(-1.75,-3.25) D2(-1.75,-2.75) D3(-1.75,-2.25) D4(-1.75,-1.75) D12(-1.75,2.25) D13(-1.75,2.75) D14(-1.75,3.25) E1(-1.25,-3.25) E2(-1.25,-2.75) E3(-1.25,-2.25) E5(-1.25,-1.25) E6(-1.25,-0.75) E7(-1.25,-0.25) E8(-1.25,0.25) E9(-1.25,0.75) E10(-1.25,1.25) E12(-1.25,2.25) E13(-1.25,2.75) E14(-1.25,3.25) F1(-0.75,-3.25) F2(-0.75,-2.75) F3(-0.75,-2.25) F5(-0.75,-1.25) F10(-0.75,1.25) F12(-0.75,2.25) F13(-0.75,2.75) F14(-0.75,3.25) G1(-0.25,-3.25) G2(-0.25,-2.75) G3(-0.25,-2.25) G5(-0.25,-1.25) G10(-0.25,1.25) G12(-0.25,2.25) G13(-0.25,2.75) G14(-0.25,3.25) H1(0.25,-3.25) H2(0.25,-2.75) H3(0.25,-2.25) H5(0.25,-1.25) H10(0.25,1.25) H12(0.25,2.25) H13(0.25,2.75) H14(0.25,3.25) J1(0.75,-3.25) J2(0.75,-2.75) J3(0.75,-2.25) J5(0.75,-1.25) J10(0.75,1.25) J12(0.75,2.25) J13(0.75,2.75) J14(0.75,3.25) K1(1.25,-3.25) K2(1.25,-2.75) K3(1.25,-2.25) K5(1.25,-1.25) K6(1.25,-0.75) K7(1.25,-0.25) K8(1.25,0.25) K9(1.25,0.75) K10(1.25,1.25) K12(1.25,2.25) K13(1.25,2.75) K14(1.25,3.25) L1(1.75,-3.25) L2(1.75,-2.75) L3(1.75,-2.25) L12(1.75,2.25) L13(1.75,2.75) L14(1.75,3.25) M1(2.25,-3.25) M2(2.25,-2.75) M3(2.25,-2.25) M4(2.25,-1.75) M5(2.25,-1.25) M6(2.25,-0.75) M7(2.25,-0.25) M8(2.25,0.25) M9(2.25,0.75) M10(2.25,1.25) M11(2.25,1.75) M12(2.25,2.25) M13(2.25,2.75) M14(2.25,3.25) N1(2.75,-3.25) N2(2.75,-2.75) N3(2.75,-2.25) N4(2.75,-1.75) N5(2.75,-1.25) N6(2.75,-0.75) N7(2.75,-0.25) N8(2.75,0.25) N9(2.75,0.75) N10(2.75,1.25) N11(2.75,1.75) N12(2.75,2.25) N13(2.75,2.75) N14(2.75,3.25) P1(3.25,-3.25) P2(3.25,-2.75) P3(3.25,-2.25) P4(3.25,-1.75) P5(3.25,-1.25) P6(3.25,-0.75) P7(3.25,-0.25) P8(3.25,0.25) P9(3.25,0.75) P10(3.25,1.25) P11(3.25,1.75) P12(3.25,2.25) P13(3.25,2.75) P14(3.25,3.25)
  silkscreen extent -6.78,-6.02 6.63,5.87
ICC_QFN56-EPAD_6P5X6P5_P040 [mm] "MCD-03000"
  rect 0.55x0.21 smd mask+0: 1(-3.245,2.6) 14(-3.245,-2.6) 29(3.245,-2.6) 42(3.245,2.6)
  rect 0.7x0.21 smd mask+0: 2(-3.17,2.2) 3(-3.17,1.8) 4(-3.17,1.4) 5(-3.17,1) 6(-3.17,0.6) 7(-3.17,0.2) 8(-3.17,-0.2) 9(-3.17,-0.6) 10(-3.17,-1) 11(-3.17,-1.4) 12(-3.17,-1.8) 13(-3.17,-2.2) 30(3.17,-2.2) 31(3.17,-1.8) 32(3.17,-1.4) 33(3.17,-1) 34(3.17,-0.6) 35(3.17,-0.2) 36(3.17,0.2) 37(3.17,0.6) 38(3.17,1) 39(3.17,1.4) 40(3.17,1.8) 41(3.17,2.2)
  rect 0.21x0.55 smd mask+0: 15(-2.6,-3.245) 28(2.6,-3.245) 43(2.6,3.245) 56(-2.6,3.245)
  rect 0.21x0.7 smd mask+0: 16(-2.2,-3.17) 17(-1.8,-3.17) 18(-1.4,-3.17) 19(-1,-3.17) 20(-0.6,-3.17) 21(-0.2,-3.17) 22(0.2,-3.17) 23(0.6,-3.17) 24(1,-3.17) 25(1.4,-3.17) 26(1.8,-3.17) 27(2.2,-3.17) 44(2.2,3.17) 45(1.8,3.17) 46(1.4,3.17) 47(1,3.17) 48(0.6,3.17) 49(0.2,3.17) 50(-0.2,3.17) 51(-0.6,3.17) 52(-1,3.17) 53(-1.4,3.17) 54(-1.8,3.17) 55(-2.2,3.17)
  rect 4.7x4.7 smd mask+0: 57(0,0)
  silkscreen extent -3.44,3 -3.01,3.42
ICC_VFBGA96_9x13_P080 [mm]
  round 0.4 smd mask+0: A1(-3.2,6) A2(-2.4,6) A3(-1.6,6) A7(1.6,6) A8(2.4,6) A9(3.2,6) B1(-3.2,5.2) B2(-2.4,5.2) B3(-1.6,5.2) B7(1.6,5.2) B8(2.4,5.2) B9(3.2,5.2) C1(-3.2,4.4) C2(-2.4,4.4) C3(-1.6,4.4) C7(1.6,4.4) C8(2.4,4.4) C9(3.2,4.4) D1(-3.2,3.6) D2(-2.4,3.6) D3(-1.6,3.6) D7(1.6,3.6) D8(2.4,3.6) D9(3.2,3.6) E1(-3.2,2.8) E2(-2.4,2.8) E3(-1.6,2.8) E7(1.6,2.8) E8(2.4,2.8) E9(3.2,2.8) F1(-3.2,2) F2(-2.4,2) F3(-1.6,2) F7(1.6,2) F8(2.4,2) F9(3.2,2) G1(-3.2,1.2) G2(-2.4,1.2) G3(-1.6,1.2) G7(1.6,1.2) G8(2.4,1.2) G9(3.2,1.2) H1(-3.2,0.4) H2(-2.4,0.4) H3(-1.6,0.4) H7(1.6,0.4) H8(2.4,0.4) H9(3.2,0.4) J1(-3.2,-0.4) J2(-2.4,-0.4) J3(-1.6,-0.4) J7(1.6,-0.4) J8(2.4,-0.4) J9(3.2,-0.4) K1(-3.2,-1.2) K2(-2.4,-1.2) K3(-1.6,-1.2) K7(1.6,-1.2) K8(2.4,-1.2) K9(3.2,-1.2) L1(-3.2,-2) L2(-2.4,-2) L3(-1.6,-2) L7(1.6,-2) L8(2.4,-2) L9(3.2,-2) M1(-3.2,-2.8) M2(-2.4,-2.8) M3(-1.6,-2.8) M7(1.6,-2.8) M8(2.4,-2.8) M9(3.2,-2.8) N1(-3.2,-3.6) N2(-2.4,-3.6) N3(-1.6,-3.6) N7(1.6,-3.6) N8(2.4,-3.6) N9(3.2,-3.6) P1(-3.2,-4.4) P2(-2.4,-4.4) P3(-1.6,-4.4) P7(1.6,-4.4) P8(2.4,-4.4) P9(3.2,-4.4) R1(-3.2,-5.2) R2(-2.4,-5.2) R3(-1.6,-5.2) R7(1.6,-5.2) R8(2.4,-5.2) R9(3.2,-5.2) T1(-3.2,-6) T2(-2.4,-6) T3(-1.6,-6) T7(1.6,-6) T8(2.4,-6) T9(3.2,-6)
  silkscreen extent -4.72,-6.55 4.55,6.73
IND_2016_MURATA_LQM2MPN2R2NG0 [mm]
  rect 0.8x1.8 smd mask+0: 1(-0.8,0) 2(0.8,0)
  silkscreen extent -0.28,-0.87 0.28,0.87
IND_2520_TOKO_DFE252012P [mm]
  rect 0.8x2 smd mask+0: 1(-1,0) 2(1,0)
  silkscreen extent -1.35,-1.12 1.35,1.12
LED_0603_OSRAM_LG-Q396-PS-35_GREEN_1A2K_H0P4 [mm]
  rect 0.8x0.8 smd mask+0: 1(-0.75,0) 2(0.75,0)
  silkscreen extent -0.85,-0.53 1.28,0.53
LINK200#1 [mm]
  rect 0.2x0.35 smd paste-10 mask+0: 1(0,-0.225)
  rect 0.2x0.35 smd paste-10 mask+0.05: 2(0,0.225)
LINK200#2 [mm]
  rect 0.2x0.35 smd paste-10 mask+0: 1(0,-0.225) 2(0,0.225)
R0201_H0P23 [mm] "MCD-00702"
  rect 0.4x0.5 smd mask+0: 1(-0.3,0) 2(0.3,0)
R0402 [mm]
  rect 0.51x0.7 smd mask+0: 1(-0.45,0) 2(0.45,0)
R0603 [mm]
  rect 0.64x1 smd mask+0: 1(-0.7,0) 2(0.7,0)
  silkscreen extent -1.05,-0.58 1.05,0.58
SWI_WE_434121025816 [mm] "MCD-03492"
  rect 1.5x1.4 smd: 1(-3.25,0) 2(3.25,0)
  silkscreen extent -3,-1.95 3,1.95
TP_SMD_1MM [mm]
  round 1 smd paste-10 mask+0: 1(0,0)
  silkscreen extent -0.7,-0.7 0.7,0.7

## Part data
B2: library part MCD-03492, "Switch tactile, SPST-NO, 50mA, 12V, 6x3.8mm"
C1 C2 C3 C4 C5 C6 C7 C8 C9 C10 C11 C12 C13 C14 C15 C16 C17 C25 C31 C44 C45 C46 C47 C52 C53 C54 C55 C56 C57 C58 C59 C60 C67: library part MCD-02377, "Capacitor, MLCC, 1uF, 6.3V, X5R, +/-20%, 0201, T=0,3mm"
C18 C42: library part MCD-01796, "Capacitor, Tantalum, 100uF, 6V3, 40mR, +/-20%,  Type_B (3528 metric), T=1.9mm"
C19 C21 C152 C157 C186 C187 C193 C204 C206 C207: library part MCD-03139, "Capacitor, MLCC, 22uF, 10V, X5R, +/-20%, 0805, T=1,25mm"
C20 C29 C30 C32 C38 C184 C199: library part MCD-00099, "Capacitor, MLCC, 10uF, 10V, X5R, +/-10%, 0603, T=0,8mm"
C22 C23 C24 C26 C27 C28 C34 C35 C36 C37 C41 C183 C200 C202: library part MCD-00100, "Capacitor, MLCC, 22uF, 6V3, X5R, +/-20%, 0603, T=0,8mm"
C33: library part MCD-00011, "Capacitor, MLCC, 10nF, 16V, X7R, 10%, 0402, T=0.5mm"
C39 C40: library part MCD-03140, "Capacitor, MLCC, 10uF, 6.3V, X5R, +/-20%, 0402, T=0.5mm"
C43 C153 C154 C188: library part MCD-00095, "Capacitor, MLCC, 1uF, 25V, X5R, +/-10%, 0402, T=0.5mm"
C48 C76 C77 C131 C132 C133 C134 C143 C146 C147 C148 C149 C159 C172 C177 C179 C182 C185 C191 C192 C194 C201 C205 C302 C304 C306 C307 C360 C361 C362 C363 C367 C373 C374 C375 C384 C390: library part MCD-00006, "Capacitor, MLCC, 100nF, 16V, X7R, +/-10%, 0402, T=0.5mm"
C61: library part MCD-01534, "Capacitor, MLCC, 4,7uF, 6V3, X5R, +/-20%, 0201, T=0.5mm"
C62 C63 C64 C65 C66 C68 C69 C70 C71 C72 C73 C74 C75 C89 C96 C97 C98 C212 C234 C275 C285: library part MCD-01535, "Capacitor, MLCC,100nF, 10V, X7R, +/-10%, 0201, T=0.3mm"
C79: library part MCD-02235, "Capacitor, MLCC, 2.2uF, 10V, X5R,+/-10%, 0201, T=0.5mm"
C80 C130 C140 C173 C364 C399: library part MCD-00099, "Capacitor, MLCC, 10uF, 10V, X5R, +/-10%, 0603, T=0.8mm"
C81 C86 C90 C92: library part MCD-00674, "Capacitor, MLCC, 6.8pF, 50V, NPO, +-0.25pF, 0402, T=0.5mm"
C87: library part MCD-00006, "Capacitor,100nF,16V,X7R,10%,0402"
C88: library part MCD-01823, "Capacitor, MLCC, 2.2uF, 6V3, X5R,+/-10%, 0402, T=0.5mm"
C91 C141 C142 C156 C189 C190 C208 C209 C217: library part MCD-01356, "Capacitor, MLCC, 4.7uF, 6V3, X5R, +/-20%, 0402, T=0.5mm"
C155: library part MCD-02198, "Capacitor, MLCC, 10nF, 50V, X7R, +/-10%, 0402, T=0.5mm"
C178 C180 C181: library part MCD-02606, "Capacitor, MLCC, 2.2uF, 6.3V, X5R, +/-10%, 0402, T=0.5mm"
CN12: library part MCD-00655, "Header 2 circuits, 1.25mm Pitch ,  Vertical, with Friction Lock"
D5: library part MCD-00034
D6: library part MCD-03280, "Diode, Schottky, Dual Common Cathode, 0V3, 300mA, 40V, SOT-23"
L1 L6: library part MCD-03143, "Inductor, 2.2uH, +/-20%, Itemp= 1700mA, Isat= 2400mA, 0R140, 0806, T=1mm"
L2 L4: library part MCD-03142, "Inductor, 0.68uH, +/-20%, Itemp= 3900mA, Isat= 5400mA, 0R031, 1008, T=1.2mm"
L3 L5 L7: library part MCD-03141, "Inductor, 0.68uH, +/-20%, Itemp= 3100mA, Isat= 4300mA, 0R043, 0806, T=1mm"
LD11: library part MCD-00588, "LED Green, 0603 SMD, Forward Voltage Typ=2V, Max=2.5V"
LNK1 LNK2 LNK4 LNK7 LNK8 LNK11: library part MCD-02777, "Track link on PCB 200um width for layout routing"
R2 R46 R57 R59 R60 R64 R75 R81 R267 R269 R286: library part MCD-00052, "Resistor,0R,0402,5%,1/16W"
R27 R37 R44 R49 R156 R248 R272: library part MCD-00053, "Resistor,10K,0402,1%,1/16W"
R66: library part MCD-00058, "Resistor, 20R, 0402, +/-1%, 1/16W"
R67: library part MCD-00052, "Resistor, 0R, 0402, +/-5%, 1/16W"
R68 R83: library part MCD-00120, "Resistor,240R,0402,1%,1/16W"
R148 R149 R150 R151 R152 R153 R154 R155 R158 R159 R160 R163 R166 R168 R170 R171 R172 R173 R174 R175 R176 R177 R178 R179 R180: library part MCD-00054, "Resistor, 56R, 0402, +/-1%, 1/16W"
R167: library part MCD-01819, "Resistor,100R,0402,0,5%,1/16W,±100ppm/°C"
R210: library part MCD-00441, "Resistor,270R,0402,1%,1/16W"
R249: library part MCD-00056, "Resistor, 0R, 0603, +/-5%, 1/10W"
R260 R261: library part MCD-00068, "Resistor,1K5,0402,1%,1/16W"
R262: library part MCD-02253, "Resistor,240R,0201,1%,1/20W"
TP9: library part MCD-00074, "Test Point 1mm"
U14 U16: library part MCD-01811, "Memory,DDR3L,4Gb,256Mbx16,933Mhz,1V35,TFBGA"
U24: library part MCD-02799, "Memory, eMMC, 4GB, 15nm ,WFBGA , 153 pins"
U26: library part MCD-03000, "STPMIC2"
U27: library part MCD-02000, "MPU, ARM Cortex-A35 + M33 32-bit MPU, 808KB RAM, With Crypto"
X1: library part MCD-01479, "Crystal, 32.768kHz, 6pF, +/-20ppm, 80K, 2.05x1.2mm"
X2: library part MCD-02344, "Crystal, 40MHz, 6pF, +/-20ppm, 80R, 1.6x1.2mm"

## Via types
v1: diameter 0.55, hole 0.35, Top Layer to Bottom Layer, 421 vias
v2: diameter 0.4, hole 0.2, Top Layer to Bottom Layer, tented both sides, 169 vias
v3: diameter 0.5, hole 0.2, Top Layer to Bottom Layer, 146 vias
v4: diameter 0.5, hole 0.25, Top Layer to Bottom Layer, 145 vias
v5: diameter 0.4, hole 0.2, Top Layer to Bottom Layer, 28 vias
